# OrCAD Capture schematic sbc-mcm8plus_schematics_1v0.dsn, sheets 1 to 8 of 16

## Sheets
1 16. Misc: size A3; title: SBC-MCM8PLUS   16. Misc; rev: 1.0; note: 8000216000
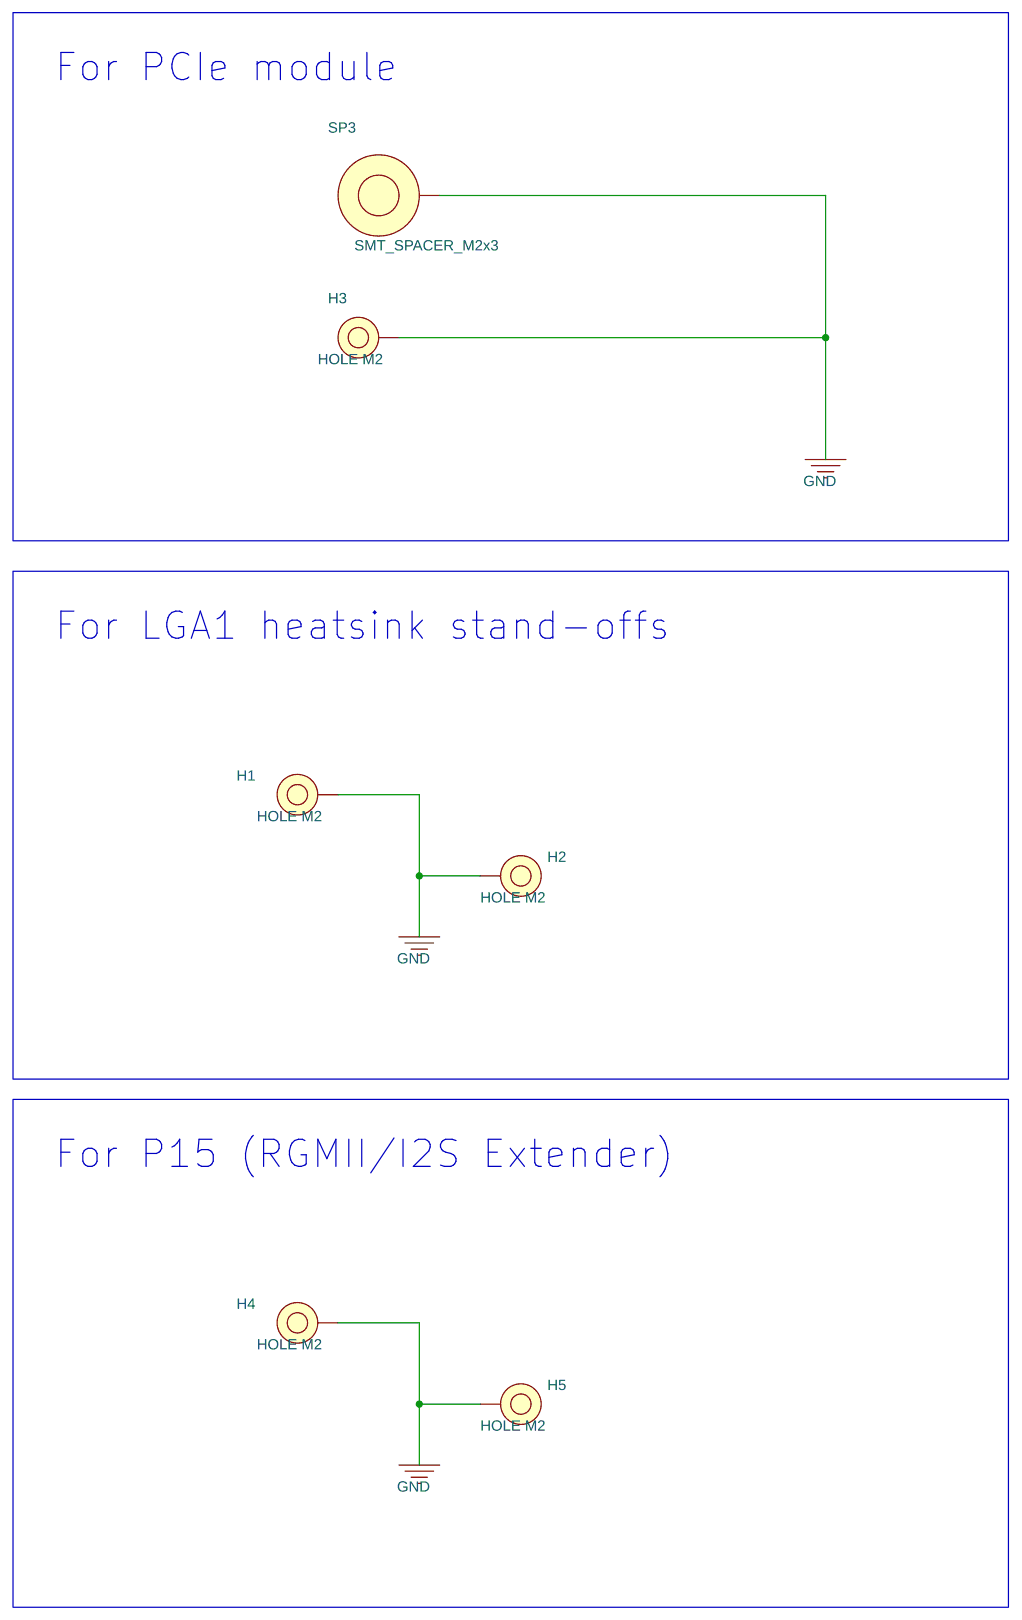
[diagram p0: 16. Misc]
2 03. Int Carrier-board interface: size A3; title: SBC-MCM8PLUS   03. Soldered Internal Interface
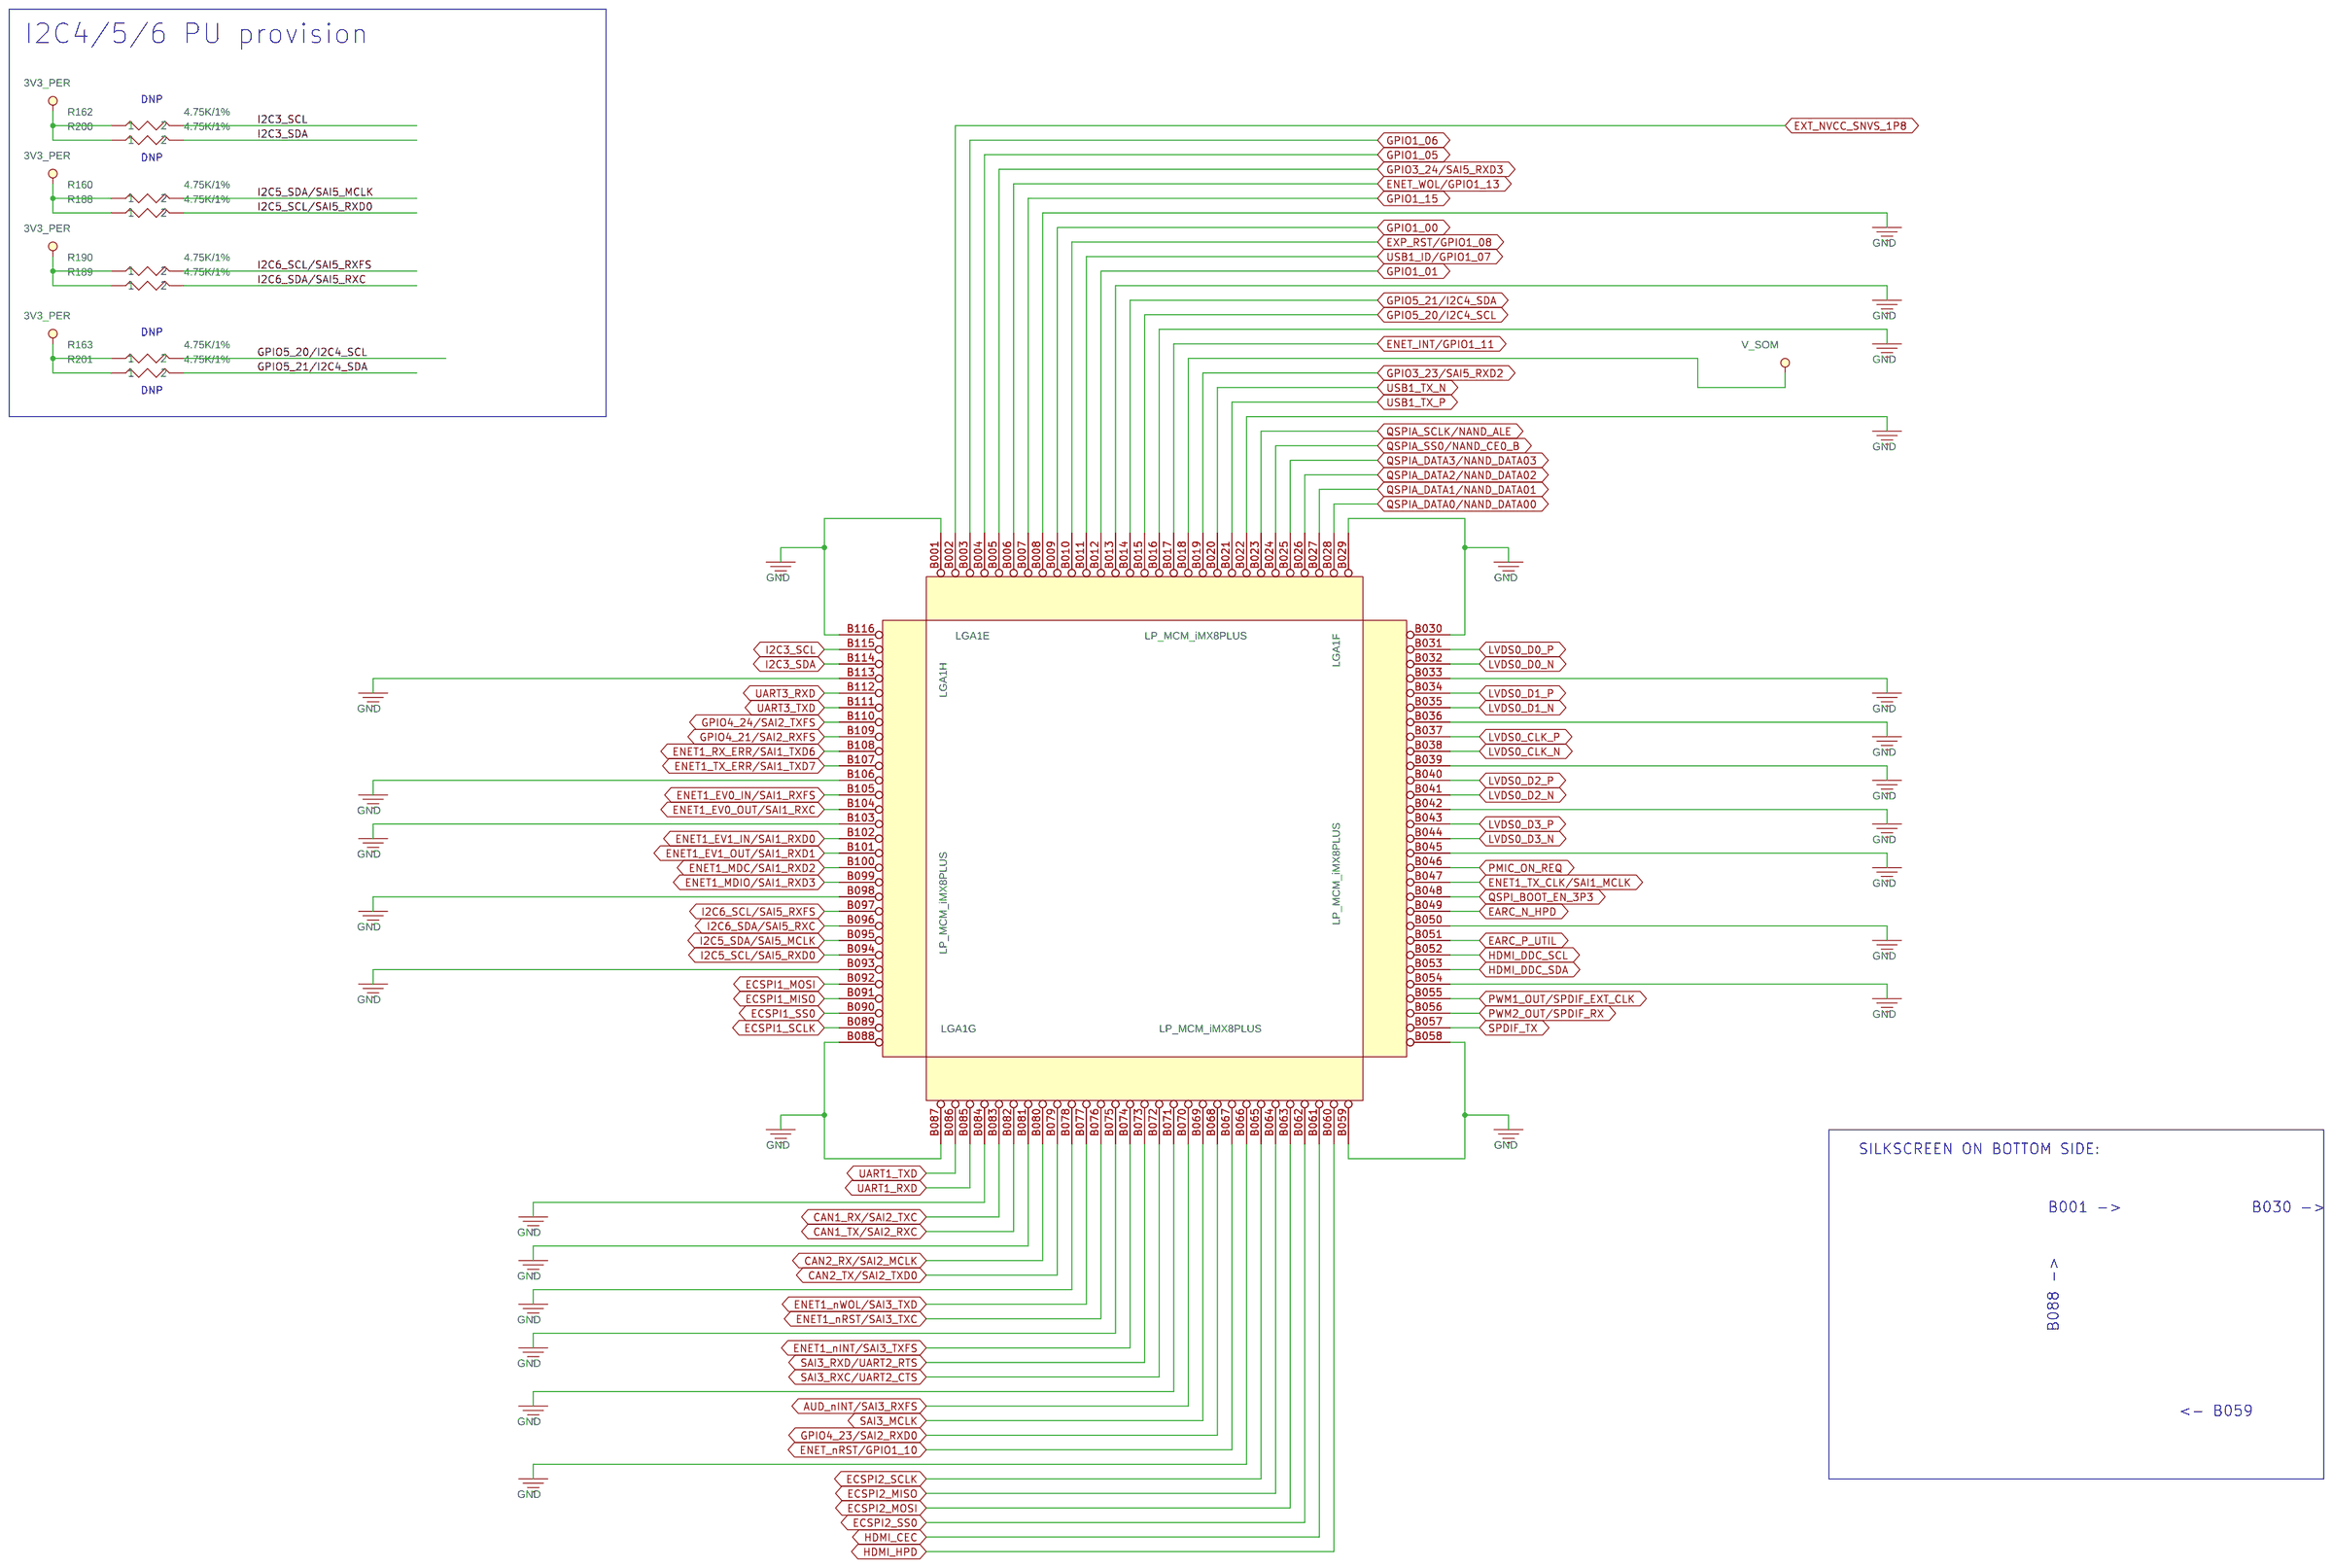
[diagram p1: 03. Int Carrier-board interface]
3 02. Ext Carrier-board interface: size A3; title: SBC-MCM8PLUS   02. Carrier
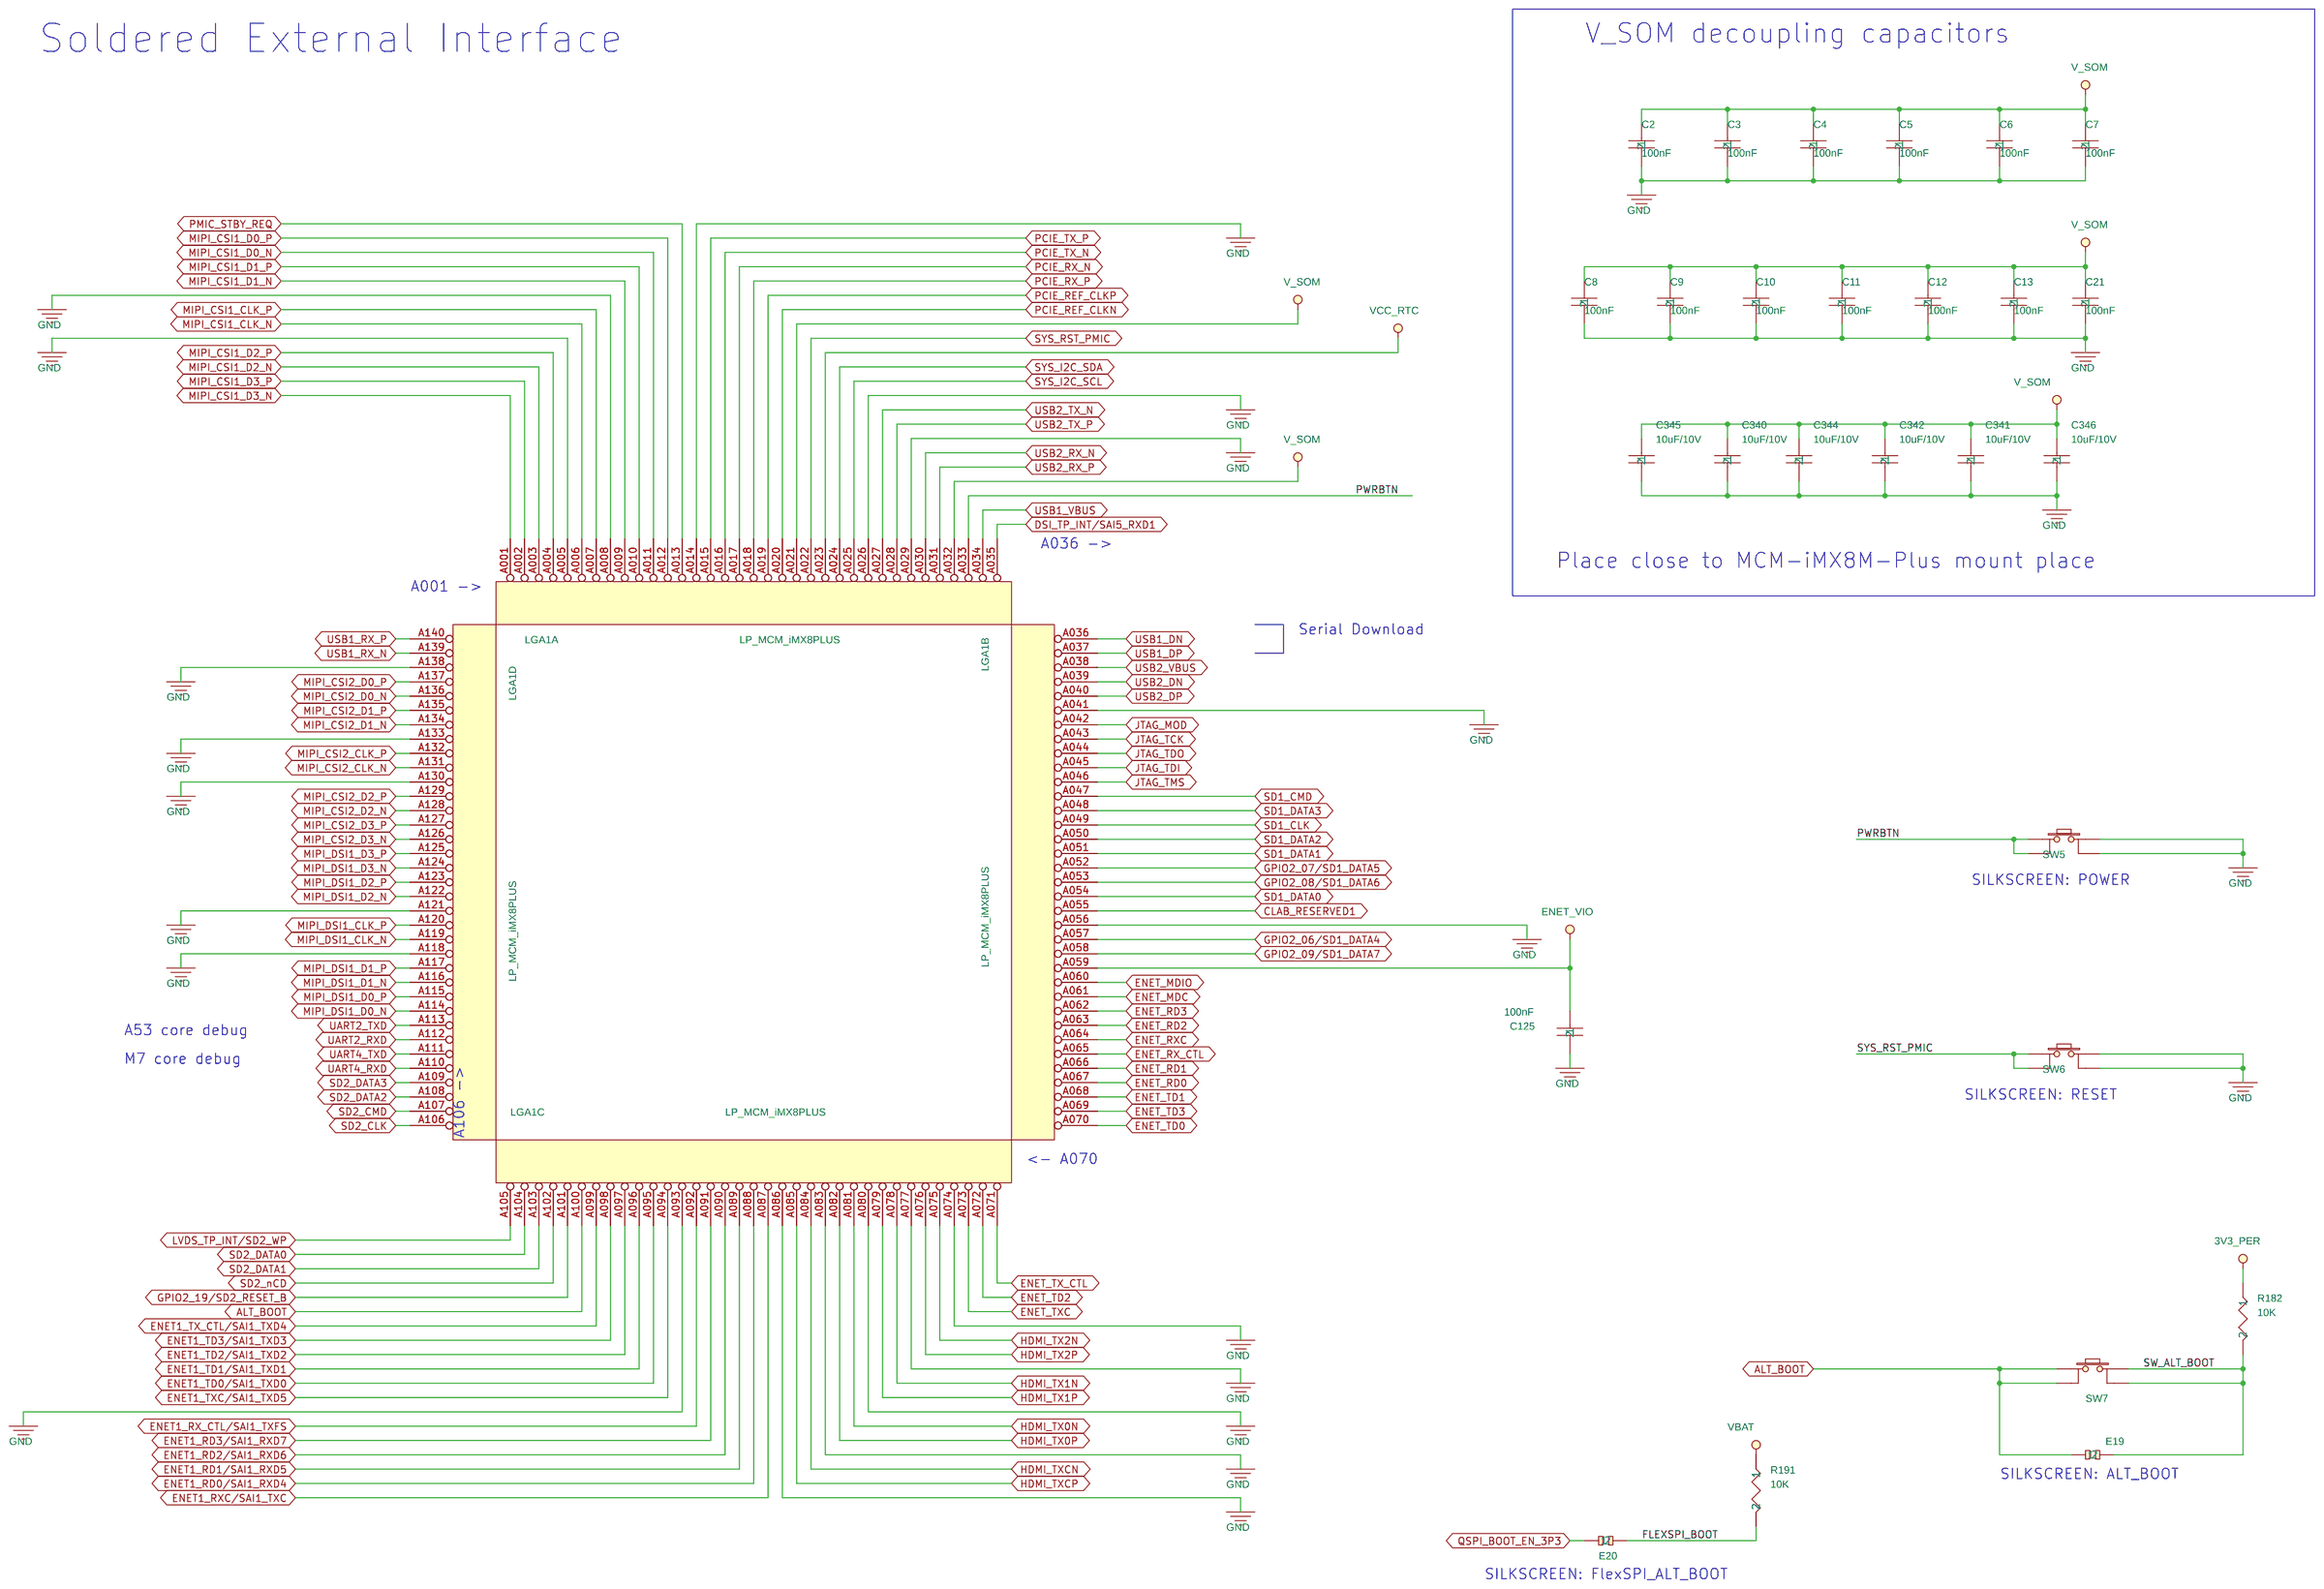
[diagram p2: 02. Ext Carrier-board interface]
4 11. MIPI-CSI2 Connectors: size A2; title: SBC-MCM8PLUS   11. MIPI-CSI2, GMSL Deserializer
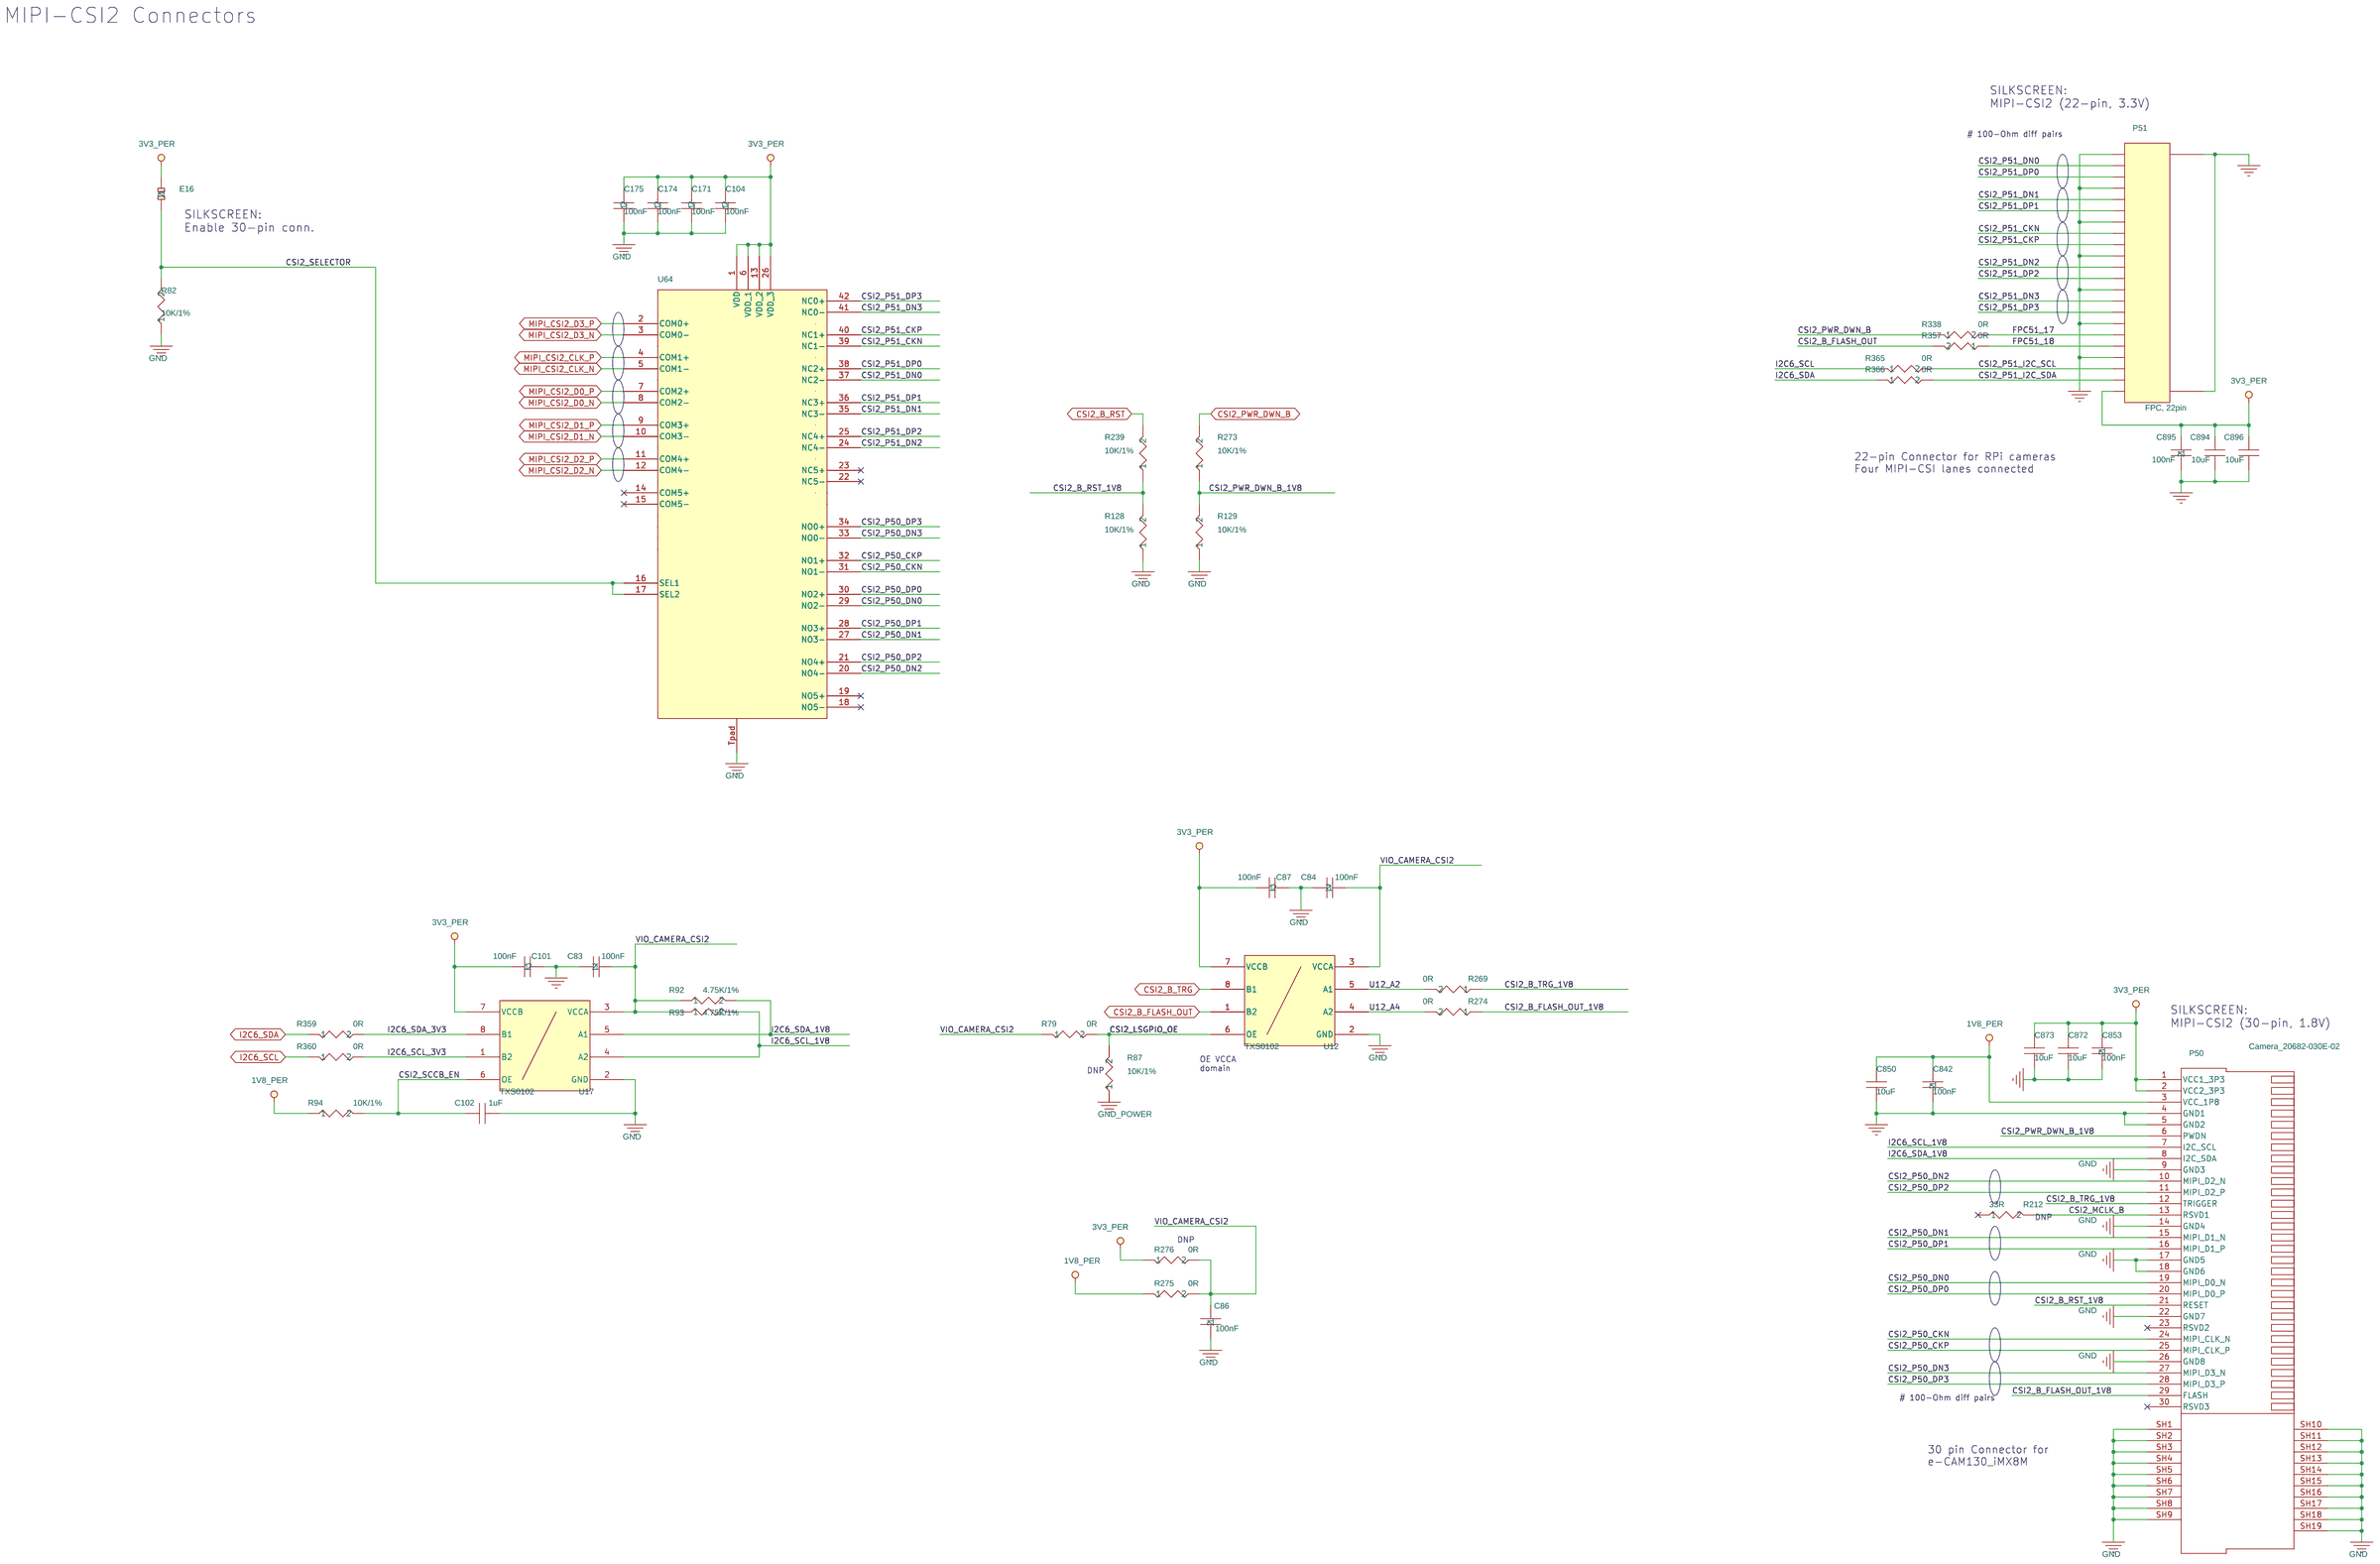
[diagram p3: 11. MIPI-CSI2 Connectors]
5 10. MIPI-CSI1 Connectors: size A3; title: SBC-MCM8PLUS   10. MIPI-CSI1 Connectors
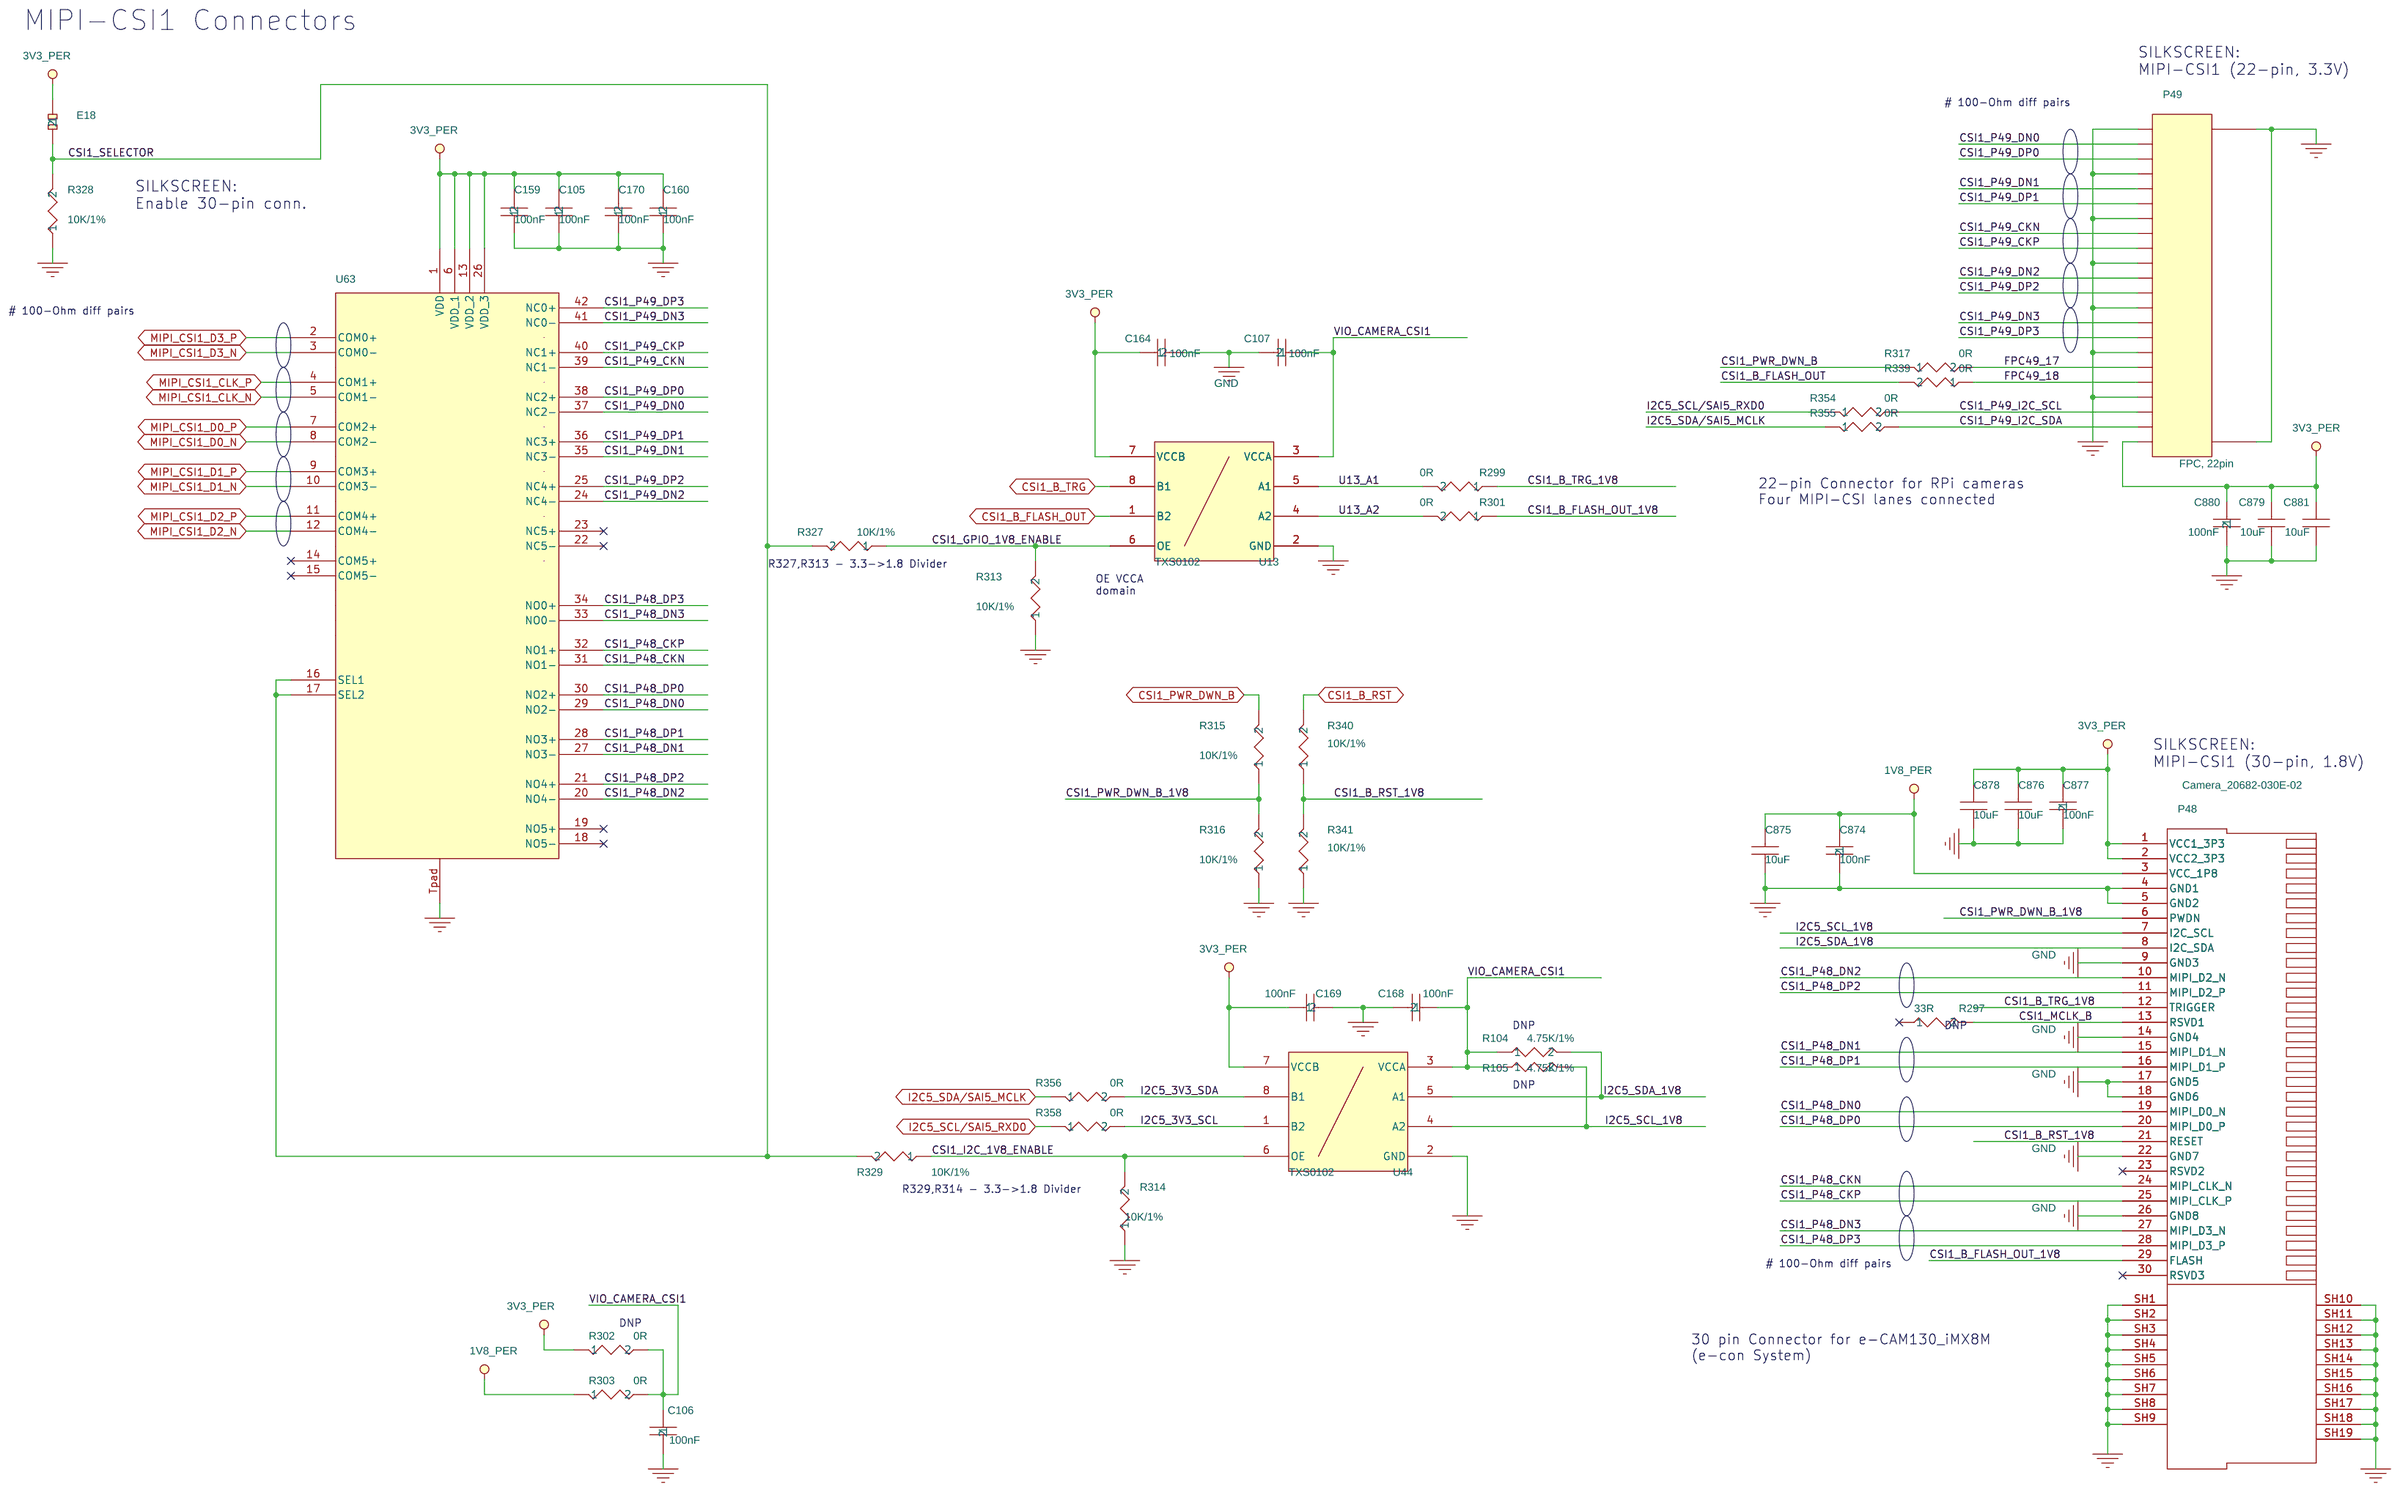
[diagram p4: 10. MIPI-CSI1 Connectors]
6 09. HDMI, eARC: size A3; title: SBC-MCM8PLUS   09. HDMI, eARC
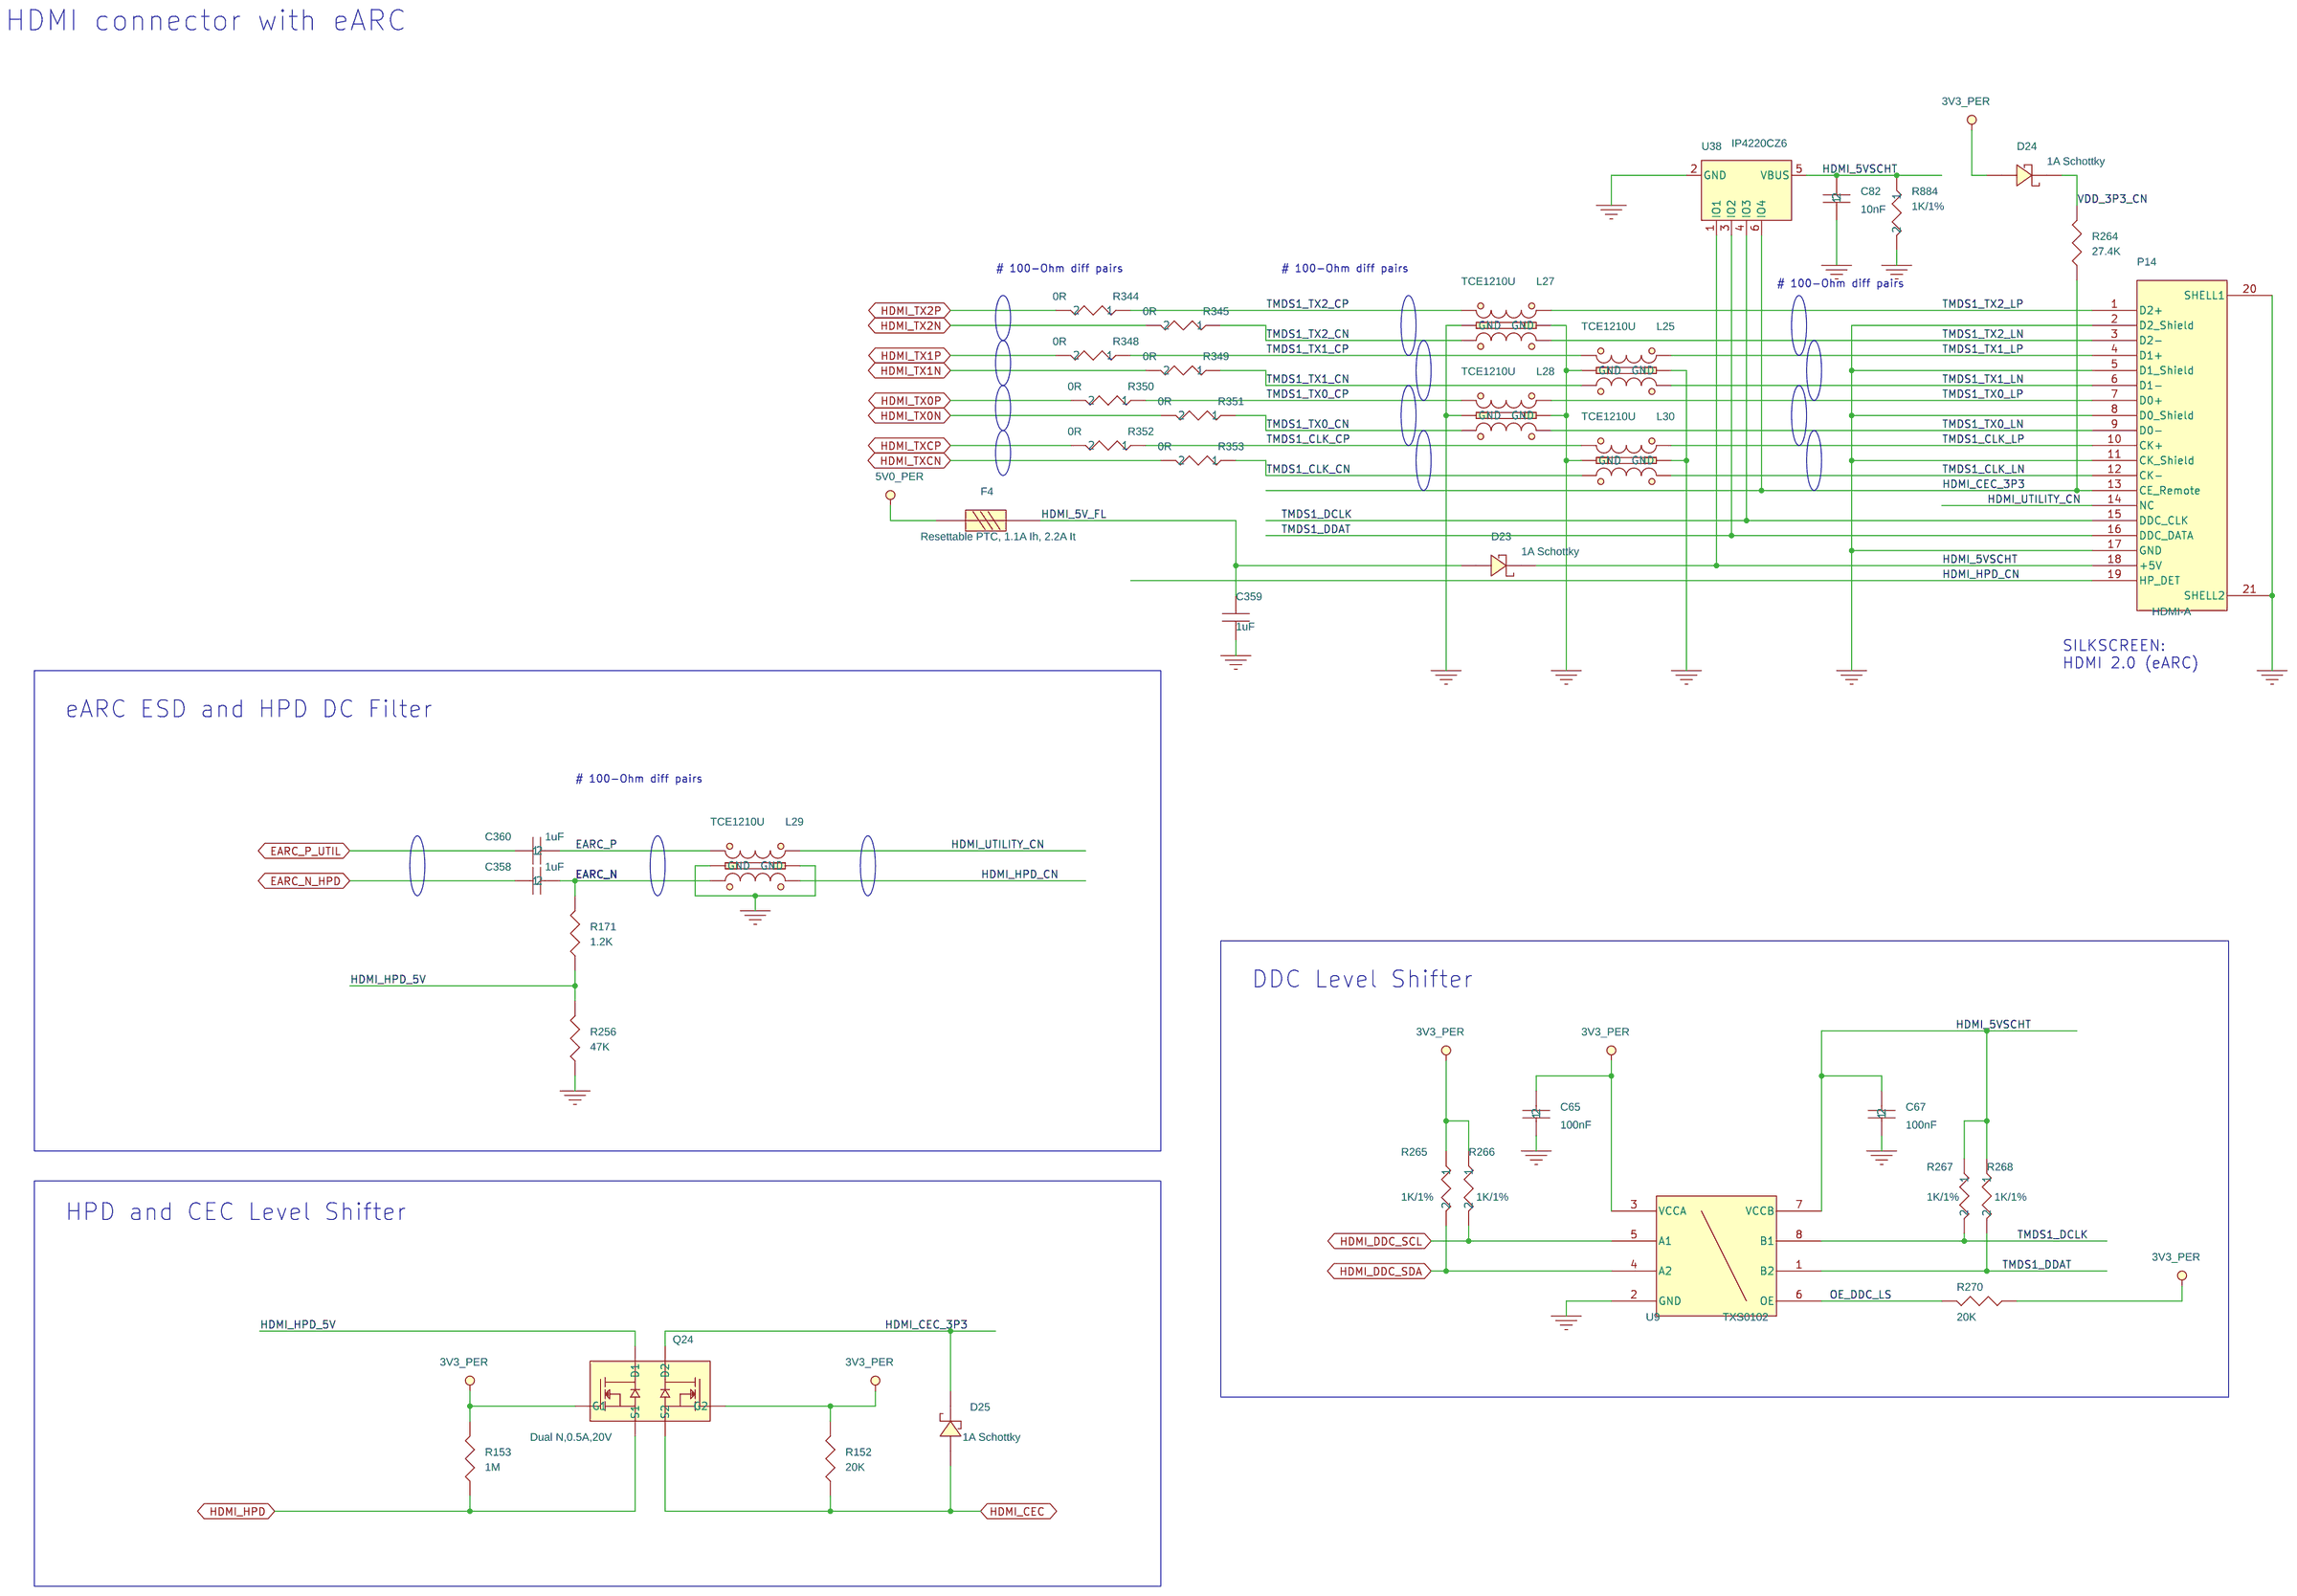
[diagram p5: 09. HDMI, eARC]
7 08. LVDS LCD: size A3; title: SBC-MCM8PLUS   08. LVDS LCD
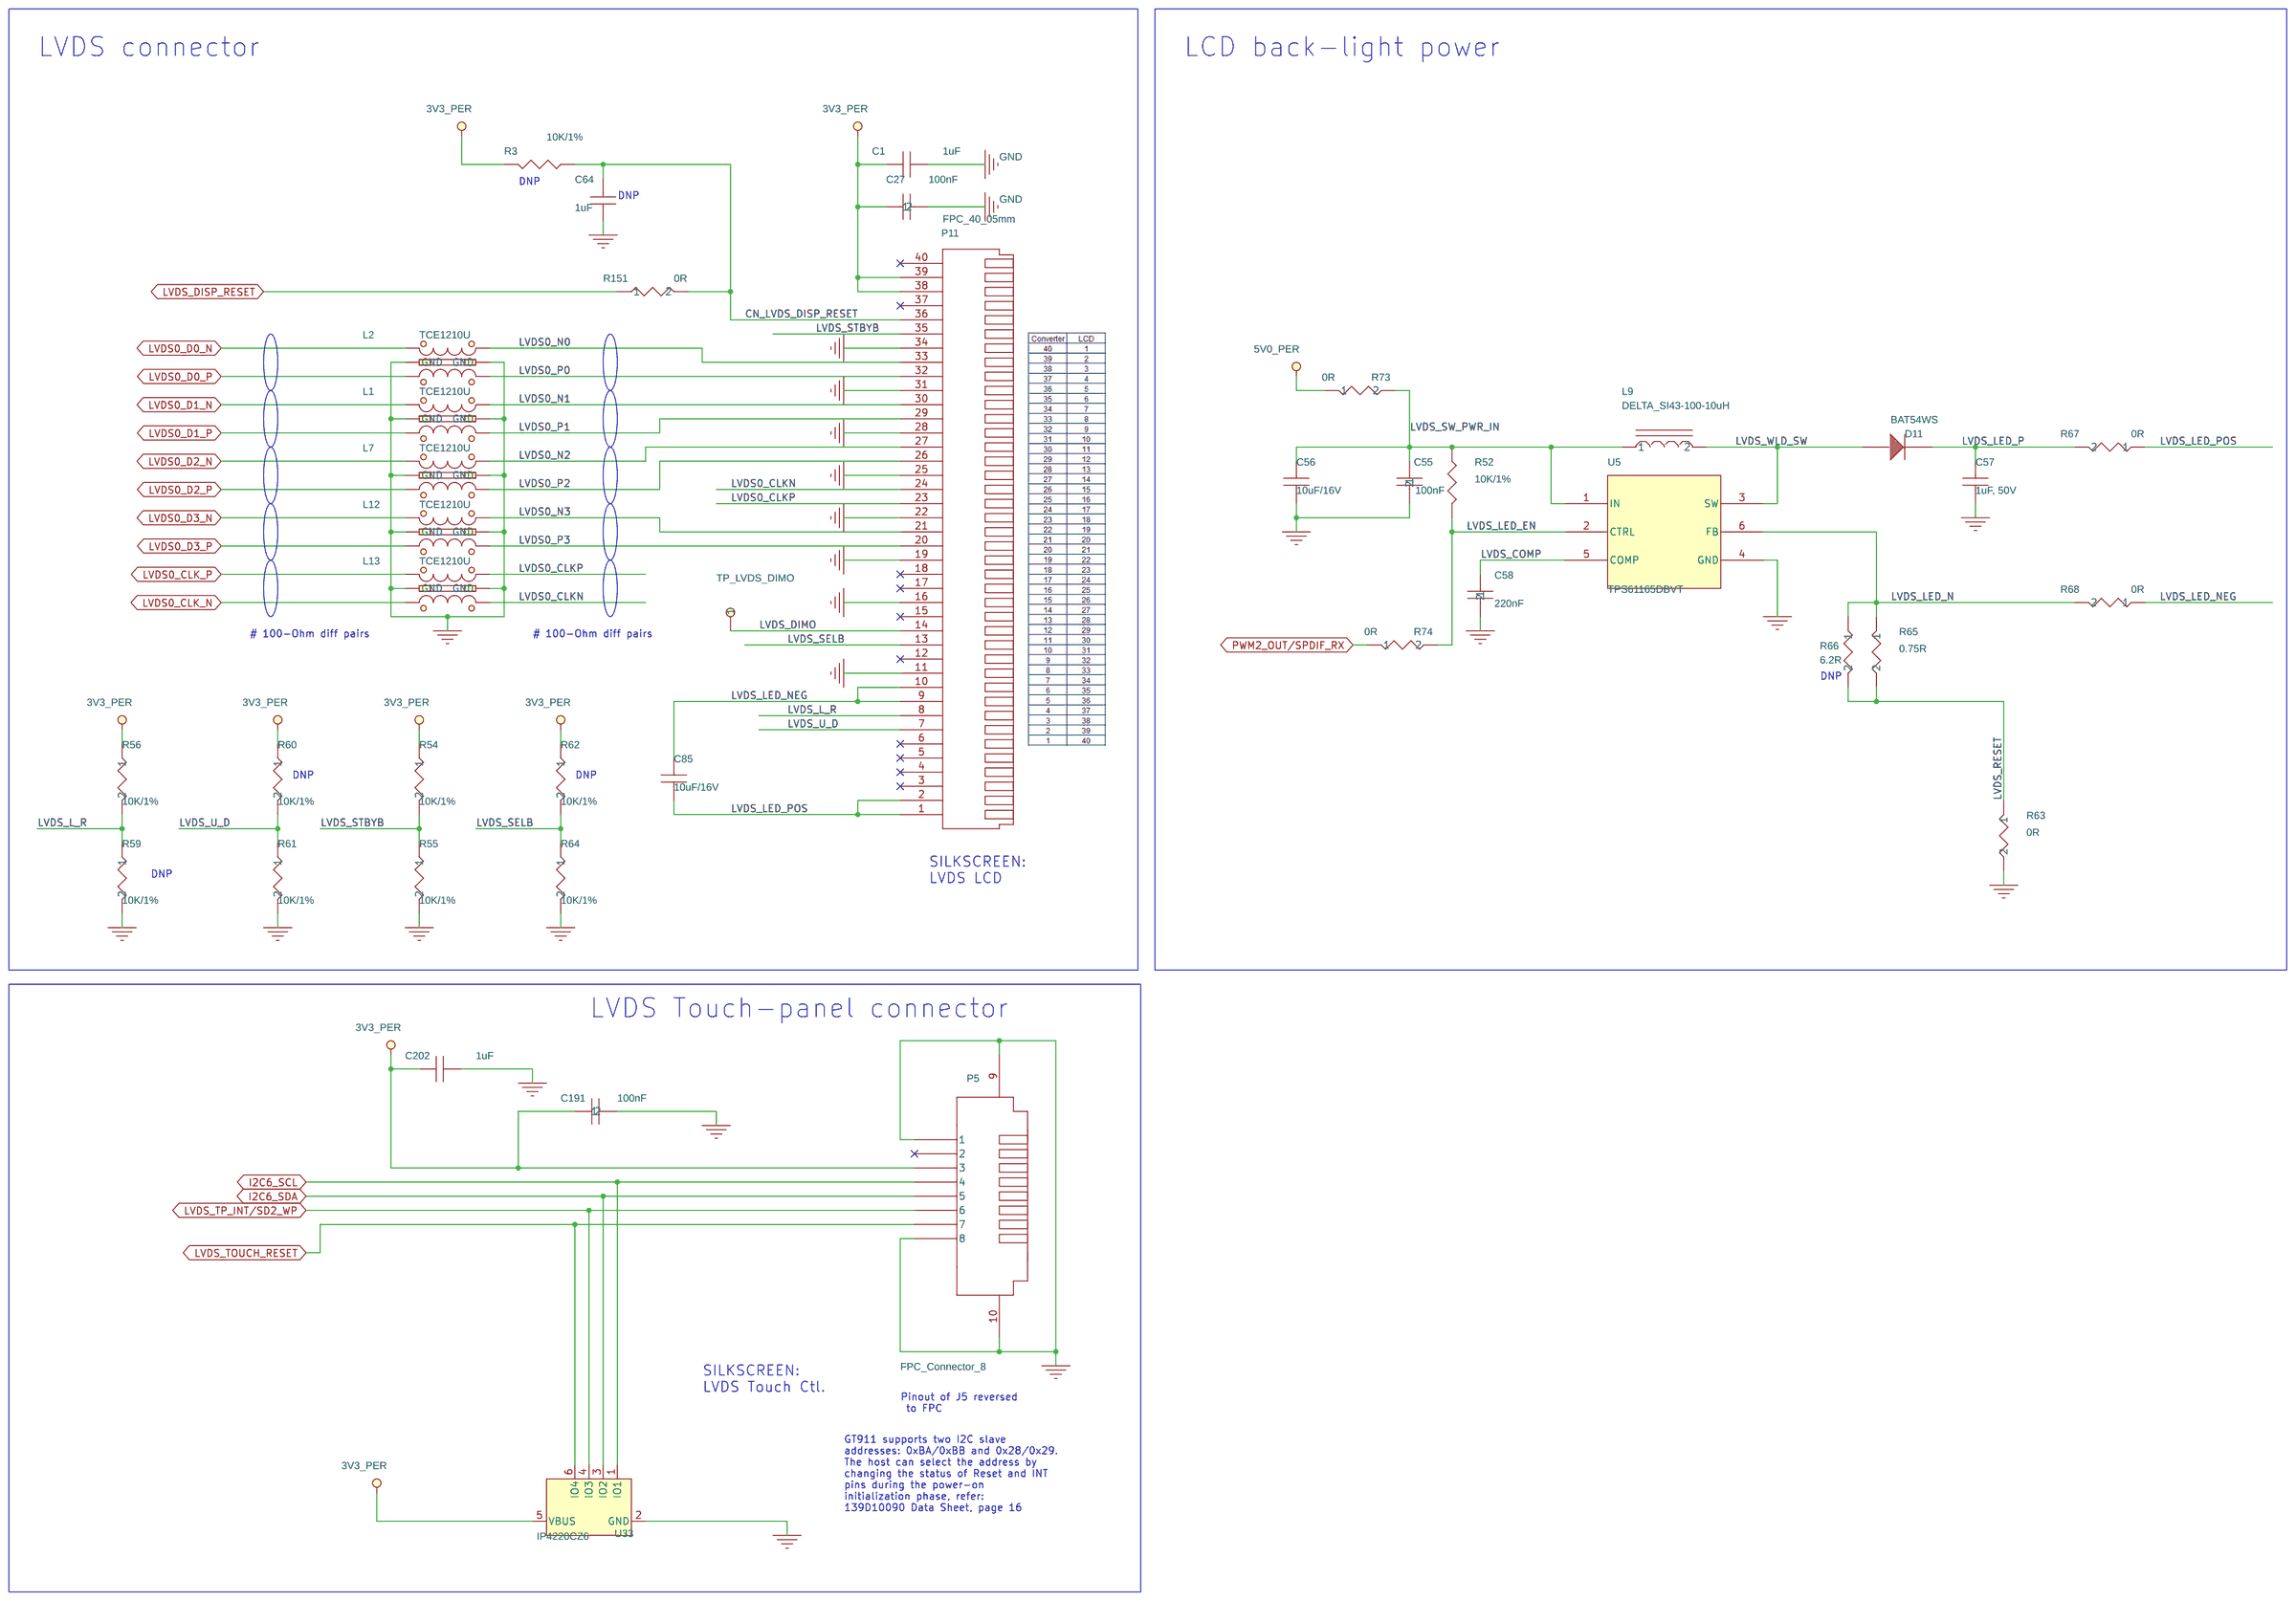
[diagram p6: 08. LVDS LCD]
8 01. Block Diagram: title: SBC-MCM8PLUS   01. INDEX
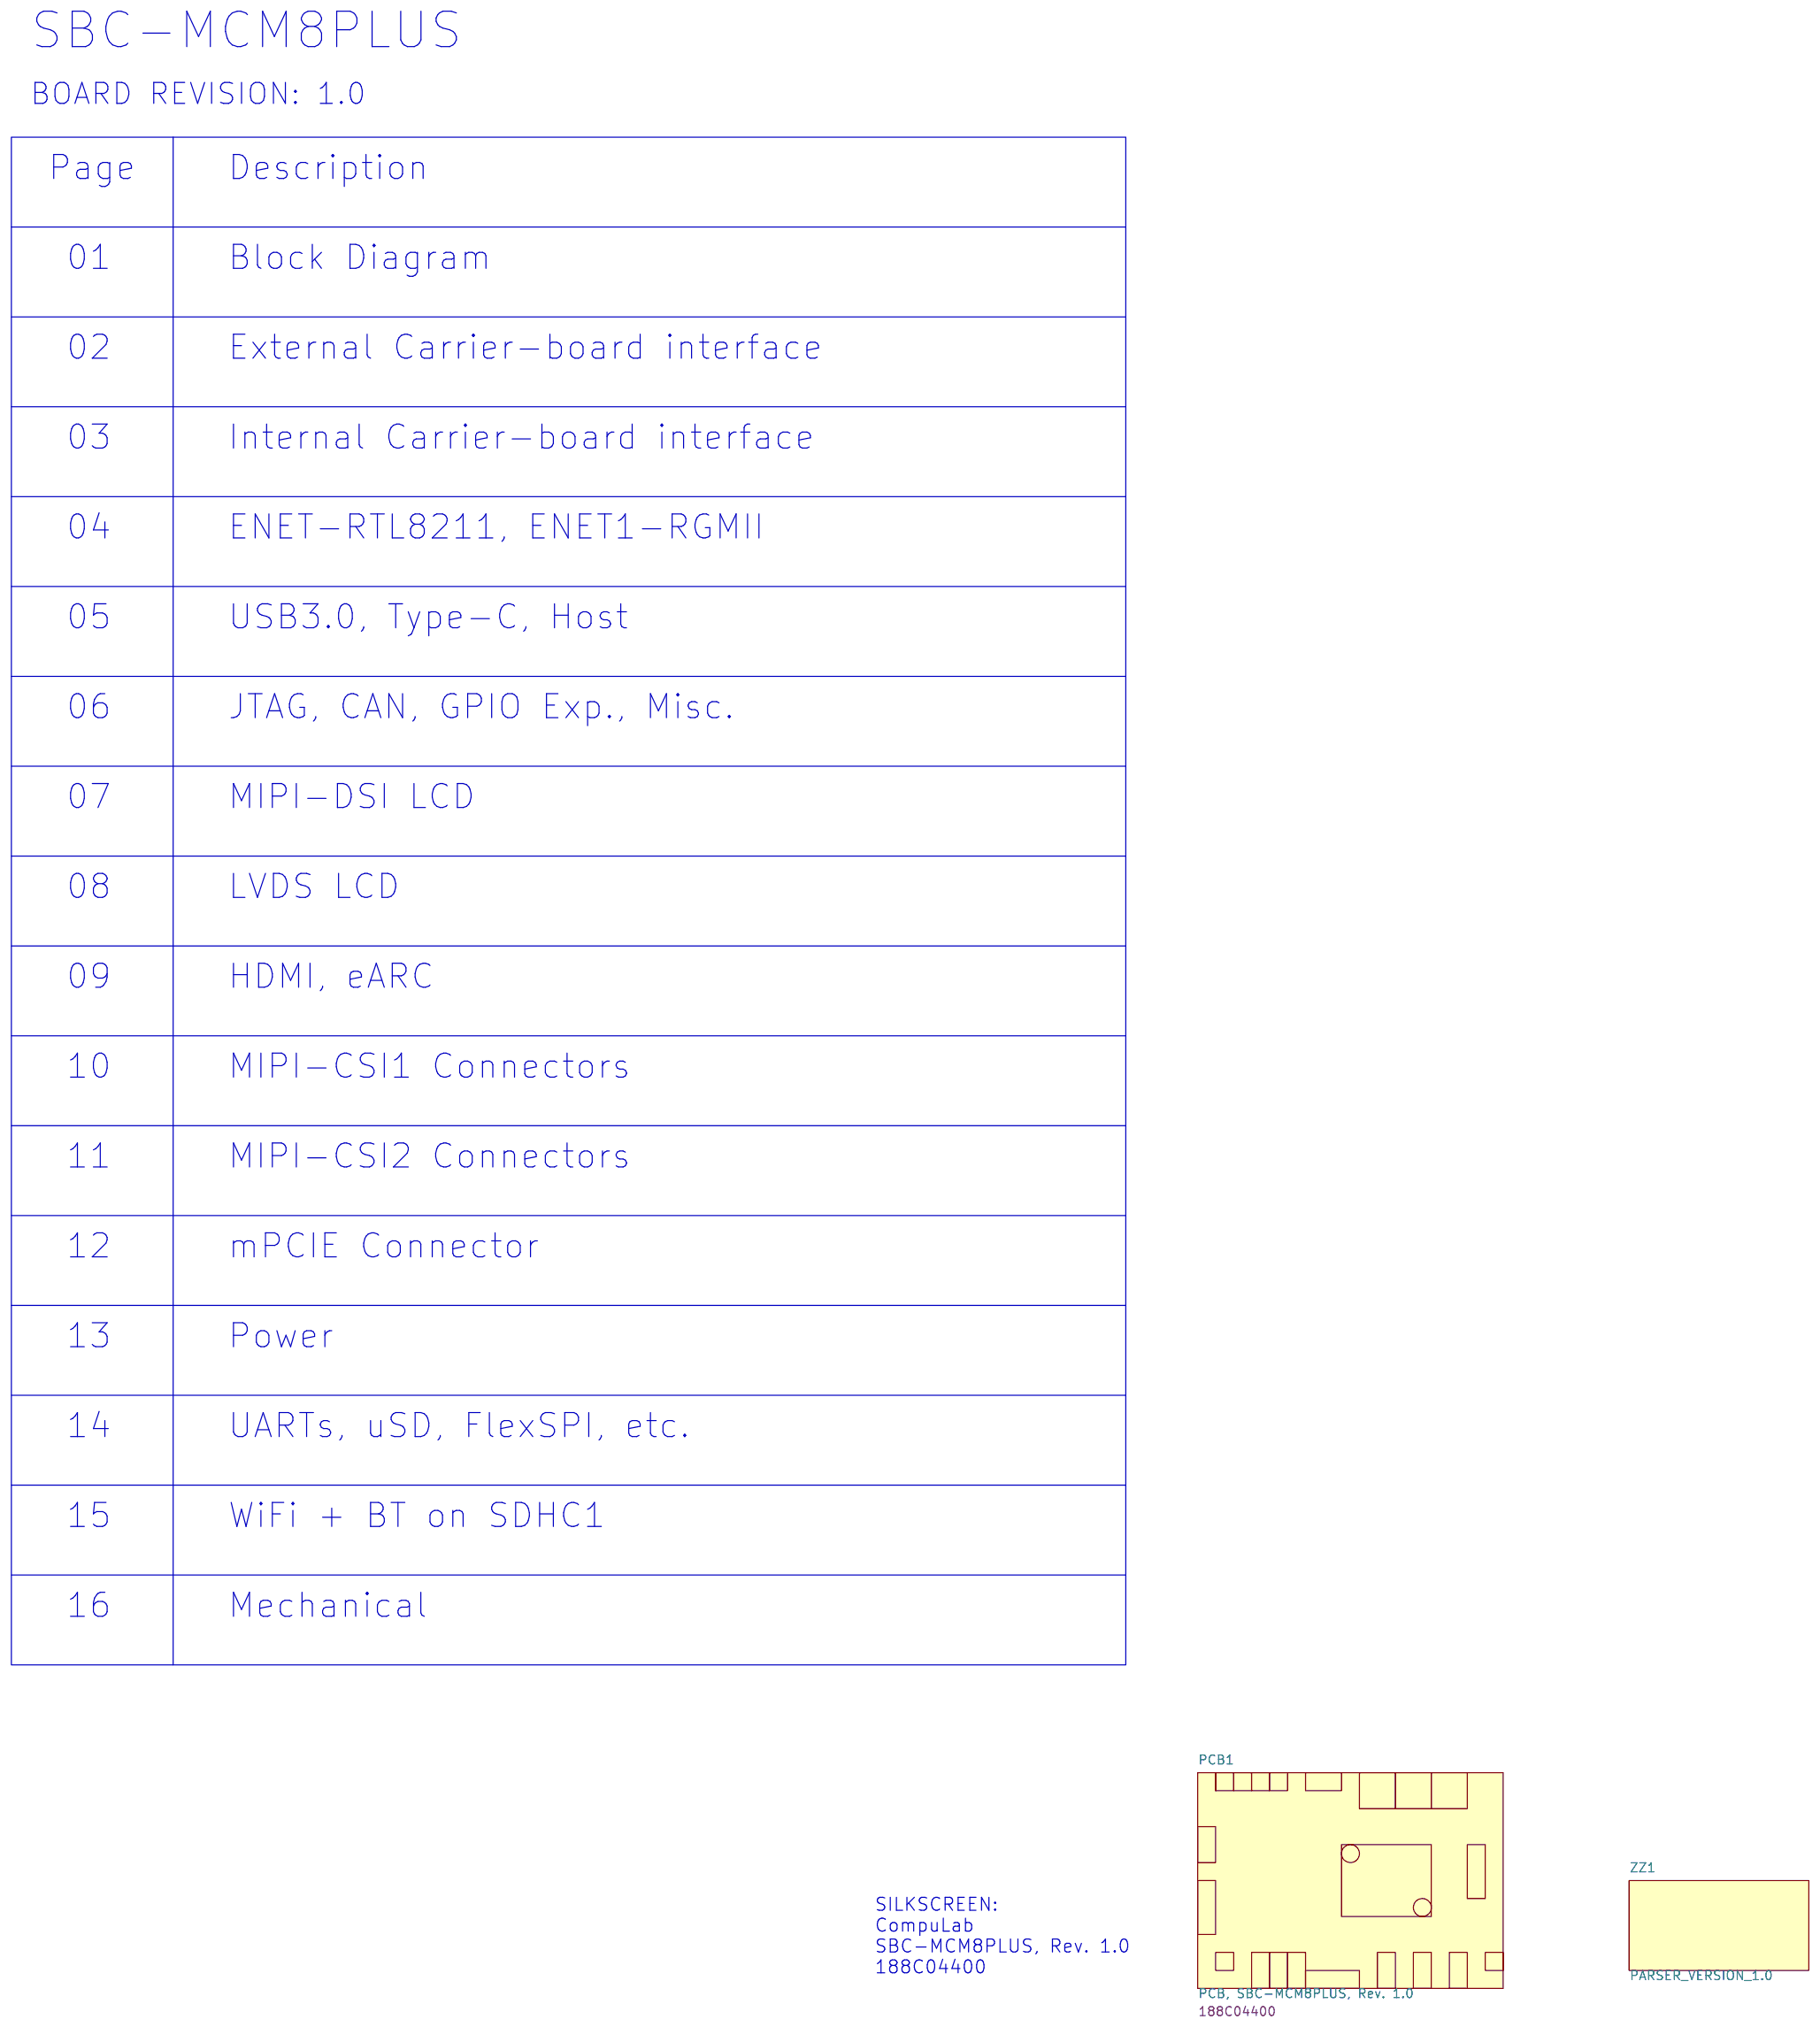
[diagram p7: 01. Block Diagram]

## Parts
sheet 01. Block Diagram
PCB1  PCB, SBC-MCM8PLUS, Rev. 1.0
ZZ1  PARSER_VERSION_1.0
sheet 02. Ext Carrier-board interface
C2  100nF  [RC0402]
C3  100nF  [RC0402]
C4  100nF  [RC0402]
C5  100nF  [RC0402]
C6  100nF  [RC0402]
C7  100nF  [RC0402]
C8  100nF  [RC0402]
C9  100nF  [RC0402]
C10  100nF  [RC0402]
C11  100nF  [RC0402]
C12  100nF  [RC0402]
C13  100nF  [RC0402]
C21  100nF  [RC0402]
C125  100nF  [RC0201]
C340  10uF/10V  [RC0402]
C341  10uF/10V  [RC0402]
C342  10uF/10V  [RC0402]
C344  10uF/10V  [RC0402]
C345  10uF/10V  [RC0402]
C346  10uF/10V  [RC0402]
E19  HDR1X2  [1X2THHDR]
E20  HDR1X2  [1X2THHDR]
R182  10K  [RC0402]
R191  10K  [RC0402]
SW5  PushB  [TACTSW6x6SM]
SW6  PushB  [TACTSW6x6SM]
SW7  PushB  [TACTSW6x6SM]
sheet 03. Int Carrier-board interface
LGA1  LP_MCM_iMX8PLUS  [LGA-256-080-30x30_Base]  (sections A,B,C,D,E,F,G,H)
R160  4.75K/1%  [RC0402]
R162  4.75K/1%  [RC0402]
R163  4.75K/1%  [RC0402]
R188  4.75K/1%  [RC0402]
R189  4.75K/1%  [RC0402]
R190  4.75K/1%  [RC0402]
R200  4.75K/1%  [RC0402]
R201  4.75K/1%  [RC0402]
sheet 08. LVDS LCD
C1  1uF  [RC0402]
C27  100nF  [RC0402]
C55  100nF  [RC0402]
C56  10uF/16V  [RC0603]
C57  1uF, 50V  [RC0603]
C58  220nF  [RC0402]
C64  1uF  [RC0402]
C85  10uF/16V  [RC0603]
C191  100nF  [RC0402]
C202  1uF  [RC0402]
D11  BAT54WS  [SOD-323]
L1  TCE1210U  [EMI1012-ESD]
L2  TCE1210U  [EMI1012-ESD]
L7  TCE1210U  [EMI1012-ESD]
L9  DELTA_SI43-100-10uH  [IND4x4x2_5]
L12  TCE1210U  [EMI1012-ESD]
L13  TCE1210U  [EMI1012-ESD]
P5  FPC_Connector_8  [FPC_8]
P11  FPC_40_05mm  [FPC05SM40-1]
R3  10K/1%  [RC0402]
R52  10K/1%  [RC0402]
R54  10K/1%  [RC0402]
R55  10K/1%  [RC0402]
R56  10K/1%  [RC0402]
R59  10K/1%  [RC0402]
R60  10K/1%  [RC0402]
R61  10K/1%  [RC0402]
R62  10K/1%  [RC0402]
R63  0R  [RC0402]
R64  10K/1%  [RC0402]
R65  0.75R  [RC0402]
R66  6.2R  [RC0402]
R67  0R  [RC1206]
R68  0R  [RC1206]
R73  0R  [RC1206]
R74  0R  [RC1206]
R151  0R  [RC0402]
TP_LVDS_DIMO  TESTPOINT  [TESTPOINT]
U5  TPS61165DBVT  [SOT23-6]
U33  IP4220CZ6  [SOT23-6L]
sheet 09. HDMI, eARC
C65  100nF  [RC0402]
C67  100nF  [RC0402]
C82  10nF  [RC0402]
C358  1uF  [RC0402]
C359  1uF  [RC0402]
C360  1uF  [RC0402]
D23  1A Schottky  [SOD-123]
D24  1A Schottky  [SOD-123]
D25  1A Schottky  [SOD-123]
F4  Resettable PTC, 1.1A Ih, 2.2A It  [FUSE-1206]
L25  TCE1210U  [EMI1012-ESD]
L27  TCE1210U  [EMI1012-ESD]
L28  TCE1210U  [EMI1012-ESD]
L29  TCE1210U  [EMI1012-ESD]
L30  TCE1210U  [EMI1012-ESD]
P14  HDMI-A  [SMT(HDMI-A)]
Q24  Dual N,0.5A,20V  [SOT-563-6]
R152  20K  [RC0402]
R153  1M  [RC0402]
R171  1.2K  [RC0402]
R256  47K  [RC0402]
R264  27.4K  [RC0402]
R265  1K/1%  [RC0402]
R266  1K/1%  [RC0402]
R267  1K/1%  [RC0402]
R268  1K/1%  [RC0402]
R270  20K  [RC0402]
R344  0R  [RC0402]
R345  0R  [RC0402]
R348  0R  [RC0402]
R349  0R  [RC0402]
R350  0R  [RC0402]
R351  0R  [RC0402]
R352  0R  [RC0402]
R353  0R  [RC0402]
R884  1K/1%  [RC0402]
U9  TXS0102  [MO-187DA-8]
U38  IP4220CZ6  [SOT23-6L]
sheet 10. MIPI-CSI1 Connectors
C105  100nF  [RC0402]
C106  100nF  [RC0402]
C107  100nF  [RC0402]
C159  100nF  [RC0402]
C160  100nF  [RC0402]
C164  100nF  [RC0402]
C168  100nF  [RC0402]
C169  100nF  [RC0402]
C170  100nF  [RC0402]
C874  100nF  [RC0402]
C875  10uF  [RC0603]
C876  10uF  [RC0603]
C877  100nF  [RC0402]
C878  10uF  [RC0603]
C879  10uF  [RC0603]
C880  100nF  [RC0402]
C881  10uF  [RC0603]
E18  HDR1X2  [1X2THHDR]
P48  Camera_20682-030E-02  [CON30]
P49  FPC, 22pin  [FPC05SM22]
R104  4.75K/1%  [RC0402]
R105  4.75K/1%  [RC0402]
R297  33R  [RC0402]
R299  0R  [RC0402]
R301  0R  [RC0402]
R302  0R  [RC0402]
R303  0R  [RC0402]
R313  10K/1%  [RC0402]
R314  10K/1%  [RC0402]
R315  10K/1%  [RC0402]
R316  10K/1%  [RC0402]
R317  0R  [RC0402]
R327  10K/1%  [RC0402]
R328  10K/1%  [RC0402]
R329  10K/1%  [RC0402]
R339  0R  [RC0402]
R340  10K/1%  [RC0402]
R341  10K/1%  [RC0402]
R354  0R  [RC0402]
R355  0R  [RC0402]
R356  0R  [RC0402]
R358  0R  [RC0402]
U13  TXS0102  [MO-187DA-8]
U44  TXS0102  [MO-187DA-8]
U63  Value  [21-0181B_T423590M-1_MXM]
sheet 11. MIPI-CSI2 Connectors
C83  100nF  [RC0402]
C84  100nF  [RC0402]
C86  100nF  [RC0402]
C87  100nF  [RC0402]
C101  100nF  [RC0402]
C102  1uF  [RC0402]
C104  100nF  [RC0402]
C171  100nF  [RC0402]
C174  100nF  [RC0402]
C175  100nF  [RC0402]
C842  100nF  [RC0402]
C850  10uF  [RC0603]
C853  100nF  [RC0402]
C872  10uF  [RC0603]
C873  10uF  [RC0603]
C894  10uF  [RC0603]
C895  100nF  [RC0402]
C896  10uF  [RC0603]
E16  HDR1X2  [1X2THHDR]
P50  Camera_20682-030E-02  [CON30]
P51  FPC, 22pin  [FPC05SM22]
R79  0R  [RC0402]
R82  10K/1%  [RC0402]
R87  10K/1%  [RC0402]
R92  4.75K/1%  [RC0402]
R93  4.75K/1%  [RC0402]
R94  10K/1%  [RC0402]
R128  10K/1%  [RC0402]
R129  10K/1%  [RC0402]
R212  33R  [RC0402]
R239  10K/1%  [RC0402]
R269  0R  [RC0402]
R273  10K/1%  [RC0402]
R274  0R  [RC0402]
R275  0R  [RC0402]
R276  0R  [RC0402]
R338  0R  [RC0402]
R357  0R  [RC0402]
R359  0R  [RC0402]
R360  0R  [RC0402]
R365  0R  [RC0402]
R366  0R  [RC0402]
U12  TXS0102  [MO-187DA-8]
U17  TXS0102  [MO-187DA-8]
U64  Value  [21-0181B_T423590M-1_MXM]
sheet 16. Misc
H1  HOLE M2  [M2PAD]
H2  HOLE M2  [M2PAD]
H3  HOLE M2  [M2PAD]
H4  HOLE M2  [M2PAD]
H5  HOLE M2  [M2PAD]
SP3  SMT_SPACER_M2x3  [MINIPCIE-4-Spacer]

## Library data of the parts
PCB1 = PCB,_EM-X270_Rev_1_6.1: CLABCONF0: = SBC-MCM8PLUS; P/N: 188C04400
ZZ1 = PARSER_VERSION_1_1.0: CLABCONF0: DNP
C2 = 100nF,_10V,_X7R,_10%,_0402_13: CLABCONF0: = SBC-MCM8PLUS; P/N: 151B10400S
C3 = 100nF,_10V,_X7R,_10%,_0402_2: CLABCONF0: = SBC-MCM8PLUS; P/N: 151B10400S
C4 = 100nF,_10V,_X7R,_10%,_0402: CLABCONF0: = SBC-MCM8PLUS; P/N: 151B10400S
C5 = 100nF,_10V,_X7R,_10%,_0402_3: CLABCONF0: = SBC-MCM8PLUS; P/N: 151B10400S
C6 = 100nF,_10V,_X7R,_10%,_0402_5: CLABCONF0: = SBC-MCM8PLUS; P/N: 151B10400S
C7 = 100nF,_10V,_X7R,_10%,_0402_6: CLABCONF0: = SBC-MCM8PLUS; P/N: 151B10400S
C8 = 100nF,_10V,_X7R,_10%,_0402_8: CLABCONF0: = SBC-MCM8PLUS; P/N: 151B10400S
C9 = 100nF,_10V,_X7R,_10%,_0402_9: CLABCONF0: = SBC-MCM8PLUS; P/N: 151B10400S
C10 = 100nF,_10V,_X7R,_10%,_0402_7: CLABCONF0: = SBC-MCM8PLUS; P/N: 151B10400S
C11 = 100nF,_10V,_X7R,_10%,_0402_10: CLABCONF0: = SBC-MCM8PLUS; P/N: 151B10400S
C12 = 100nF,_10V,_X7R,_10%,_0402_12: CLABCONF0: = SBC-MCM8PLUS; P/N: 151B10400S
C13 = 100nF,_10V,_X7R,_10%,_0402_1: CLABCONF0: = SBC-MCM8PLUS; P/N: 151B10400S
C21 = 100nF,_10V,_X7R,_10%,_0402_4: CLABCONF0: = SBC-MCM8PLUS; P/N: 151B10400S
C125 = 100nF,_10V,_X7R,_10%,_0402_11: CLABCONF0: = SBC-MCM8PLUS; P/N: 151B104B0S
C340 = 10uF_10V_20%_0402_3: CLABCONF0: = SBC-MCM8PLUS
C341 = 10uF_10V_20%_0402_5: CLABCONF0: = SBC-MCM8PLUS
C342 = 10uF_10V_20%_0402: CLABCONF0: = SBC-MCM8PLUS
C344 = 10uF_10V_20%_0402_4: CLABCONF0: = SBC-MCM8PLUS
C345 = 10uF_10V_20%_0402_1: CLABCONF0: = SBC-MCM8PLUS
C346 = 10uF_10V_20%_0402_2: CLABCONF0: = SBC-MCM8PLUS
E19 = HDR_1x2_100MIL_TH_JUMPER_1: CLABCONF0: = SBC-MCM8PLUS
E16 E18 E20 = HDR_1x2_100MIL_TH_JUMPER: CLABCONF0: = SBC-MCM8PLUS
R182 = 1M_,5%,_0402: CLABCONF0: = SBC-MCM8PLUS; P/N: 161C10021S
R191 = 1M_,5%,_0402_1: CLABCONF0: = SBC-MCM8PLUS; P/N: 161C10021S
SW5-SW7 = TACT_SW_6x6mm_SMT: CLABCONF0: = SBC-MCM8PLUS
LGA1 = LP_MCM_iMX8PLUS: CLABCONF0: 503M015060=CQMD4N32; Color: Default; Location X-Coordinate: 0; Location Y-Coordinate: 0; P/N: 503M015060; Power Pins Visible: False; Primitive: DEFAULT
R160 = 4_0.75K,1%,0402,1_16W_2: CLABCONF0: = SBC-MCM8PLUS
R104 R162 = 4_0.75K,1%,0402,1_16W_1: CLABCONF0: DNP
R163 = 4_0.75K,1%,0402,1_16W_7: CLABCONF0: DNP
R188 = 4_0.75K,1%,0402,1_16W_3: CLABCONF0: = SBC-MCM8PLUS
R189 = 4_0.75K,1%,0402,1_16W_4: CLABCONF0: = SBC-MCM8PLUS
R190 = 4_0.75K,1%,0402,1_16W_6: CLABCONF0: = SBC-MCM8PLUS
R105 R200 = 4_0.75K,1%,0402,1_16W: CLABCONF0: DNP
R201 = 4_0.75K,1%,0402,1_16W_5: CLABCONF0: DNP
C1 C102 C202 = 1uF,X5R,6.3V,0402: CLABCONF0: = SBC-MCM8PLUS
C27 C174 C874 = 100nF,_10V,_X7R,_10%,_0402: CLABCONF0: = SBC-MCM8PLUS
C55 C65 C169 C842 = 100nF,_10V,_X7R,_10%,_0402_3: CLABCONF0: = SBC-MCM8PLUS
C56 = 10uF,6.3V,0603,20%X5R_1: CLABCONF0: = SBC-MCM8PLUS
C57 = 1uF,X5R,6.3V,0402: CLABCONF0: = SBC-MCM8PLUS; P/N: 151D10510S
C58 = 100nF,_10V,_X7R,_10%,_0402_2: CLABCONF0: = SBC-MCM8PLUS; P/N: 151C22400S
C64 = 1uF,X5R,6.3V,0402: CLABCONF0: DNP
C85 = 10uF,6.3V,0603,20%X5R: CLABCONF0: = SBC-MCM8PLUS
C67 C160 C175 C191 = 100nF,_10V,_X7R,_10%,_0402_1: CLABCONF0: = SBC-MCM8PLUS
D11 = BAT54WS_0: CLABCONF0: = SBC-MCM8PLUS
L1 L2 L7 L12 L13 L25 L27-L30 = ESD_CHOKE_DIFFx2_10: CLABCONF0: = SBC-MCM8PLUS; P/N: 142D11801S
L9 = INC_DELTA_SI43-100,_10uH: CLABCONF0: = SBC-MCM8PLUS; CLABCONF1: <null>
P5 = FPC_Connector_6: CLABCONF0: = SBC-MCM8PLUS; P/N: 182P00803S
P11 = FPC_40_05mm: CLABCONF0: = SBC-MCM8PLUS; P/N: 182P04001S
R3 = 10K,1%,0402,1_16W_0_1: CLABCONF0: DNP
R52 = 10K,1%,0402,1_16W_0: CLABCONF0: = SBC-MCM8PLUS
R54 R129 R329 = 10K,1%,0402,1_16W_3: CLABCONF0: = SBC-MCM8PLUS
R55 = 10K,1%,0402,1_16W_5: CLABCONF0: DNP
R56 R273 R341 = 10K,1%,0402,1_16W_6: CLABCONF0: = SBC-MCM8PLUS
R59 = 10K,1%,0402,1_16W_7: CLABCONF0: DNP
R60 R87 = 10K,1%,0402,1_16W: CLABCONF0: DNP
R61 R82 R316 = 10K,1%,0402,1_16W_1: CLABCONF0: = SBC-MCM8PLUS
R62 = 10K,1%,0402,1_16W_2: CLABCONF0: DNP
R63 = 2.2R,5%,0402,1_16W_1: CLABCONF0: = SBC-MCM8PLUS; P/N: 161C00005S
R64 R239 R327 = 10K,1%,0402,1_16W_4: CLABCONF0: = SBC-MCM8PLUS
R65 = 2.2R,5%,0402,1_16W_2: CLABCONF0: = SBC-MCM8PLUS; P/N: 161C0R751S
R66 = 2.2R,5%,0402,1_16W: CLABCONF0: DNP; P/N: 161C06R25S
R67 = 0R,_1206: CLABCONF0: = SBC-MCM8PLUS
R68 = 0R,_1206_1: CLABCONF0: = SBC-MCM8PLUS
R73 = 0R,_1206_3: CLABCONF0: = SBC-MCM8PLUS
R74 = 0R,_1206_2: CLABCONF0: = SBC-MCM8PLUS
R151 = 0R,_0402: CLABCONF0: = SBC-MCM8PLUS
TP_LVDS_DIMO = TESTPOINT: CLABCONF0: DNP
U5 = TPS61165DBVT: CLABCONF0: = SBC-MCM8PLUS; P/N: 123C15100S
U33 U38 = IP4220CZ6_0: CLABCONF0: = SBC-MCM8PLUS
C82 = 10nF,_25V,_X7R,_10%,_0402: CLABCONF0: = SBC-MCM8PLUS
C358 = 100nF,_10V,_X7R,_10%,_0402_2: CLABCONF0: = SBC-MCM8PLUS; P/N: 151C10500S
C359 = Cap_1uF,X5R,6.3V,0402: CLABCONF0: = SBC-MCM8PLUS
C360 = 100nF,_10V,_X7R,_10%,_0402: CLABCONF0: = SBC-MCM8PLUS; P/N: 151C10500S
D23-D25 = 1A_Schottky_Barrier_Rectifier: CLABCONF0: = SBC-MCM8PLUS
F4 = Fuse,_0.75A_Ih,_1.5A_It: CLABCONF0: = SBC-MCM8PLUS; P/N: 175P22200S
P14 = HDMI_Connector: CLABCONF0: = SBC-MCM8PLUS
Q24 = DUAL_N-MOSFET,_0.5A_20V: CLABCONF0: = SBC-MCM8PLUS
R152 R270 = RESISTOR: CLABCONF0: = SBC-MCM8PLUS; P/N: 161C20021S
R153 = RESISTOR: CLABCONF0: = SBC-MCM8PLUS; P/N: 161C10045S
R171 = RESISTOR: CLABCONF0: = SBC-MCM8PLUS; P/N: 161C12011S
R256 = RESISTOR: CLABCONF0: = SBC-MCM8PLUS; P/N: 161C47025S
R264 = RESISTOR: CLABCONF0: = SBC-MCM8PLUS; P/N: 161C27421S
R265 = 1K,1%,0402,1_16W_1: CLABCONF0: = SBC-MCM8PLUS
R266 = 1K,1%,0402,1_16W_2: CLABCONF0: = SBC-MCM8PLUS
R267 = 1K,1%,0402,1_16W_3: CLABCONF0: = SBC-MCM8PLUS
R268 = 1K,1%,0402,1_16W: CLABCONF0: = SBC-MCM8PLUS
R344 = 0R,_0402_1_4: CLABCONF0: = SBC-MCM8PLUS
R299 R345 R357 = 0R,_0402_1_2: CLABCONF0: = SBC-MCM8PLUS
R269 R339 R348 = 0R,_0402_1_1: CLABCONF0: = SBC-MCM8PLUS
R349 = 0R,_0402_1_6: CLABCONF0: = SBC-MCM8PLUS
R350 = 0R,_0402_1_5: CLABCONF0: = SBC-MCM8PLUS
R274 R301 R351 = 0R,_0402_1: CLABCONF0: = SBC-MCM8PLUS
R352 = 0R,_0402_1_3: CLABCONF0: = SBC-MCM8PLUS
R353 = 0R,_0402_1_7: CLABCONF0: = SBC-MCM8PLUS
R884 = 1K,1%,0402,1_16W_4: CLABCONF0: = SBC-MCM8PLUS
U9 U12 U13 U17 U44 = TXS0102_0: CLABCONF0: = SBC-MCM8PLUS; P/N: 116A01020S
C101 C105 = 100nF,_10V,_X7R,_10%,_0402_2: CLABCONF0: = SBC-MCM8PLUS
C106 C171 = 100nF,_10V,_X7R,_10%,_0402_10: CLABCONF0: = SBC-MCM8PLUS
C107 C853 = 100nF,_10V,_X7R,_10%,_0402_6: CLABCONF0: = SBC-MCM8PLUS
C104 C159 = 100nF,_10V,_X7R,_10%,_0402_8: CLABCONF0: = SBC-MCM8PLUS
C86 C164 = 100nF,_10V,_X7R,_10%,_0402_11: CLABCONF0: = SBC-MCM8PLUS
C84 C168 = 100nF,_10V,_X7R,_10%,_0402_5: CLABCONF0: = SBC-MCM8PLUS
C170 C895 = 100nF,_10V,_X7R,_10%,_0402_7: CLABCONF0: = SBC-MCM8PLUS
C850 C872 C873 C875 C876 C878 C879 C881 C894 C896 = 10uF,6_0.3V,0603,20%X5R: CLABCONF0: = SBC-MCM8PLUS
C87 C877 = 100nF,_10V,_X7R,_10%,_0402_9: CLABCONF0: = SBC-MCM8PLUS
C83 C880 = 100nF,_10V,_X7R,_10%,_0402_4: CLABCONF0: = SBC-MCM8PLUS
P48 P50 = Camera_20682-030E-02: CLABCONF0: = SBC-MCM8PLUS; P/N: 182K03002S
P49 P51 = FPC,_0.5mm,_22_cont_0.: CLABCONF0: = SBC-MCM8PLUS; P/N: 182P02201S
R212 R297 = 33R,5%,0402,1_16W: CLABCONF0: DNP
R276 R302 = 0R,_0402_0_3: CLABCONF0: DNP; P/N: 161C00005S
R303 R338 = 0R,_0402_0_6: CLABCONF0: = SBC-MCM8PLUS; P/N: 161C00005S
R313 = 10K,1%,0402,1_16W_7: CLABCONF0: = SBC-MCM8PLUS
R314 = 10K,1%,0402,1_16W_8: CLABCONF0: = SBC-MCM8PLUS
R94 R315 = 10K,1%,0402,1_16W_5: CLABCONF0: = SBC-MCM8PLUS
R79 R317 = 0R,_0402_0_5: CLABCONF0: = SBC-MCM8PLUS; P/N: 161C00005S
R128 R328 = 10K,1%,0402,1_16W_2: CLABCONF0: = SBC-MCM8PLUS
R340 = 10K,1%,0402,1_16W: CLABCONF0: = SBC-MCM8PLUS
R354 R366 = 0R,_0402_0_2: CLABCONF0: = SBC-MCM8PLUS; P/N: 161C00005S
R275 R355 = 0R,_0402_0_1: CLABCONF0: = SBC-MCM8PLUS; P/N: 161C00005S
R356 R359 = 0R,_0402_0_4: CLABCONF0: = SBC-MCM8PLUS; P/N: 161C00005S
R358 R365 = 0R,_0402_0: CLABCONF0: = SBC-MCM8PLUS; P/N: 161C00005S
U63 U64 = MAX14998ETOT: CLABCONF0: = SBC-MCM8PLUS
R92 = 4_0.75K,1%,0402,1_16W_1: CLABCONF0: = SBC-MCM8PLUS
R93 = 4_0.75K,1%,0402,1_16W: CLABCONF0: = SBC-MCM8PLUS
R360 = 0R,_0402_0_7: CLABCONF0: = SBC-MCM8PLUS; P/N: 161C00005S
H1-H5 = Hole,_Plated,_M2,_5mm._ext.: CLABCONF0: DNP
SP3 = SMT_SPACER_M2x3_1: CLABCONF0: = SBC-MCM8PLUS

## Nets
1V8_PER: C842.1 C850.1 C874.1 C875.1 P48.3(VCC_1P8) P50.3(VCC_1P8) R94.1 R275.1 R303.1 ; also on sheet 9 10 12 13 14 15
3V3_PER: C1.1 C27.1 C65.2 C87.1 C101.1 C104.2 C105.2 C159.2 C160.2 C164.1 C169.1 C170.2 C171.2 C174.2 C175.2 C191.1 C202.1 C853.1 C872.1 C873.1 C876.1 C877.1 C878.1 C879.1 C880.1 C881.1 C894.1 C895.1 C896.1 D24.2(ANODE) E16.1 E18.1 P5.3 P11.38 P11.39 P48.1(VCC1_3P3) P48.2(VCC2_3P3) P49.22 P50.1(VCC1_3P3) P50.2(VCC2_3P3) P51.22 Q24.2(G1) Q24.5(G2) R3.2 R54.1 R56.1 R60.1 R62.1 R152.2 R153.2 R160.1 R162.1 R163.1 R182.1 R188.1 R189.1 R190.1 R191.1 R200.1 R201.1 R265.1 R266.1 R270.1 R276.1 R302.1 U9.3(VCCA) U12.7(VCCB) U13.7(VCCB) U17.7(VCCB) U33.5(VBUS) U44.7(VCCB) U63.1(VDD) U63.6(VDD_1) U63.13(VDD_2) U63.26(VDD_3) U64.1(VDD) U64.6(VDD_1) U64.13(VDD_2) U64.26(VDD_3) ; also on sheet 9 10 11 12 13 14 15 16
5V0_PER: F4.2 R73.1 ; also on sheet 9 10 13 14 16
GND: C1.2 C2.2 C3.2 C4.2 C5.2 C6.2 C7.2 C8.2 C9.2 C10.2 C11.2 C12.2 C13.2 C21.2 C27.2 C55.2 C56.2 C57.2 C58.2 C64.1 C65.1 C67.1 C82.1 C83.2 C84.2 C86.2 C87.2 C101.2 C102.2 C104.1 C105.1 C106.2 C107.2 C125.2 C159.1 C160.1 C164.2 C168.2 C169.2 C170.1 C171.1 C174.1 C175.1 C191.2 C202.2 C340.2 C341.2 C342.2 C344.2 C345.2 C346.2 C359.2 C842.2 C850.2 C853.2 C872.2 C873.2 C874.2 C875.2 C876.2 C877.2 C878.2 C879.2 C880.2 C881.2 C894.2 C895.2 C896.2 H1.1 H2.1 H3.1 H4.1 H5.1 L1.5(GND) L1.6(GND) L2.5(GND) L2.6(GND) L7.5(GND) L7.6(GND) L12.5(GND) L12.6(GND) L13.5(GND) L13.6(GND) L25.5(GND) L25.6(GND) L27.5(GND) L27.6(GND) L28.5(GND) L28.6(GND) L29.5(GND) L29.6(GND) L30.5(GND) L30.6(GND) LGA1.A005 LGA1.A008 LGA1.A014 LGA1.A026 LGA1.A029 LGA1.A041 LGA1.A056 LGA1.A074 LGA1.A077 LGA1.A080 LGA1.A083 LGA1.A086 LGA1.A093 LGA1.A118 LGA1.A121 LGA1.A130 LGA1.A133 LGA1.A138 LGA1.B001 LGA1.B008 LGA1.B013 LGA1.B016 LGA1.B022 LGA1.B029 LGA1.B030 LGA1.B033 LGA1.B036 LGA1.B039 LGA1.B042 LGA1.B045 LGA1.B050 LGA1.B054 LGA1.B058 LGA1.B059 LGA1.B066 LGA1.B071 LGA1.B075 LGA1.B078 LGA1.B081 LGA1.B084 LGA1.B087 LGA1.B088 LGA1.B093 LGA1.B098 LGA1.B103 LGA1.B106 LGA1.B113 LGA1.B116 P5.1 P5.8 P5.9 P5.10 P11.11 P11.16 P11.19 P11.22 P11.25 P11.28 P11.31 P11.34 P14.2(D2_Shield) P14.5(D1_Shield) P14.8(D0_Shield) P14.11(CK_Shield) P14.17(GND) P14.20(SHELL1) P14.21(SHELL2) P48.4(GND1) P48.5(GND2) P48.9(GND3) P48.14(GND4) P48.17(GND5) P48.18(GND6) P48.22(GND7) P48.26(GND8) P48.SH1 P48.SH2 P48.SH3 P48.SH4 P48.SH5 P48.SH6 P48.SH7 P48.SH8 P48.SH9 P48.SH10 P48.SH11 P48.SH12 P48.SH13 P48.SH14 P48.SH15 P48.SH16 P48.SH17 P48.SH18 P48.SH19 P49.1 P49.4 P49.7 P49.10 P49.13 P49.16 P49.19 P49.NC1 P49.NC2 P50.4(GND1) P50.5(GND2) P50.9(GND3) P50.14(GND4) P50.17(GND5) P50.18(GND6) P50.22(GND7) P50.26(GND8) P50.SH1 P50.SH2 P50.SH3 P50.SH4 P50.SH5 P50.SH6 P50.SH7 P50.SH8 P50.SH9 P50.SH10 P50.SH11 P50.SH12 P50.SH13 P50.SH14 P50.SH15 P50.SH16 P50.SH17 P50.SH18 P50.SH19 P51.1 P51.4 P51.7 P51.10 P51.13 P51.16 P51.19 P51.NC1 P51.NC2 R55.2 R59.2 R61.2 R63.2 R64.2 R82.1 R87.1 R128.1 R129.1 R256.1 R313.1 R314.1 R316.1 R328.1 R341.1 R884.2 SP3.NC(1) SW5.1 SW5.3 SW6.1 SW6.3 U5.4(GND) U9.2(GND) U12.2(GND) U13.2(GND) U17.2(GND) U33.2(GND) U38.2(GND) U44.2(GND) U63.Tpad U64.Tpad ; also on sheet 9 10 11 12 13 14 15 16
VCC_RTC: LGA1.A023 ; also on sheet 13
VDD_3P3_CN: D24.1(CATHODE) R264.2
ALT_BOOT: E19.1 LGA1.A100 SW7.2 SW7.4
AUD_nINT/SAI3_RXFS: LGA1.B070 ; also on sheet 9
CAN1_RX/SAI2_TXC: LGA1.B083 ; also on sheet 10
CAN1_TX/SAI2_RXC: LGA1.B082 ; also on sheet 10
CAN2_RX/SAI2_MCLK: LGA1.B080 ; also on sheet 10
CAN2_TX/SAI2_TXD0: LGA1.B079 ; also on sheet 10
CLAB_RESERVED1: LGA1.A055 ; also on sheet 15
CN_LVDS_DISP_RESET: C64.2 P11.36 R3.1 R151.2
CSI1_B_FLASH_OUT: R339.2 U13.1(B2) ; also on sheet 10
CSI1_B_FLASH_OUT_1V8: P48.29(FLASH) R301.1
CSI1_B_RST: R340.2 ; also on sheet 10
CSI1_B_RST_1V8: P48.21(RESET) R340.1 R341.2
CSI1_B_TRG: U13.8(B1) ; also on sheet 10
CSI1_B_TRG_1V8: P48.12(TRIGGER) R299.1
CSI1_GPIO_1V8_ENABLE: R313.2 R327.1 U13.6(OE)
CSI1_I2C_1V8_ENABLE: R314.2 R329.1 U44.6(OE)
CSI1_MCLK_B: P48.13(RSVD1) R297.2
CSI1_P48_CKN: P48.24(MIPI_CLK_N) U63.31(NO1-)
CSI1_P48_CKP: P48.25(MIPI_CLK_P) U63.32(NO1+)
CSI1_P48_DN0: P48.19(MIPI_D0_N) U63.29(NO2-)
CSI1_P48_DN1: P48.15(MIPI_D1_N) U63.27(NO3-)
CSI1_P48_DN2: P48.10(MIPI_D2_N) U63.20(NO4-)
CSI1_P48_DN3: P48.27(MIPI_D3_N) U63.33(NO0-)
CSI1_P48_DP0: P48.20(MIPI_D0_P) U63.30(NO2+)
CSI1_P48_DP1: P48.16(MIPI_D1_P) U63.28(NO3+)
CSI1_P48_DP2: P48.11(MIPI_D2_P) U63.21(NO4+)
CSI1_P48_DP3: P48.28(MIPI_D3_P) U63.34(NO0+)
CSI1_P49_CKN: P49.8 U63.39(NC1-)
CSI1_P49_CKP: P49.9 U63.40(NC1+)
CSI1_P49_DN0: P49.2 U63.37(NC2-)
CSI1_P49_DN1: P49.5 U63.35(NC3-)
CSI1_P49_DN2: P49.11 U63.24(NC4-)
CSI1_P49_DN3: P49.14 U63.41(NC0-)
CSI1_P49_DP0: P49.3 U63.38(NC2+)
CSI1_P49_DP1: P49.6 U63.36(NC3+)
CSI1_P49_DP2: P49.12 U63.25(NC4+)
CSI1_P49_DP3: P49.15 U63.42(NC0+)
CSI1_P49_I2C_SCL: P49.20 R354.2
CSI1_P49_I2C_SDA: P49.21 R355.2
CSI1_PWR_DWN_B: R315.2 R317.1 ; also on sheet 10
CSI1_PWR_DWN_B_1V8: P48.6(PWDN) R315.1 R316.2
CSI1_SELECTOR: E18.2 R327.2 R328.2 R329.2 U63.16(SEL1) U63.17(SEL2)
CSI2_B_FLASH_OUT: R357.2 U12.1(B2) ; also on sheet 10
CSI2_B_FLASH_OUT_1V8: P50.29(FLASH) R274.1
CSI2_B_RST: R239.2 ; also on sheet 10
CSI2_B_RST_1V8: P50.21(RESET) R128.2 R239.1
CSI2_B_TRG: U12.8(B1) ; also on sheet 10
CSI2_B_TRG_1V8: P50.12(TRIGGER) R269.1
CSI2_LSGPIO_OE: R79.2 R87.2 U12.6(OE)
CSI2_MCLK_B: P50.13(RSVD1) R212.2
CSI2_P50_CKN: P50.24(MIPI_CLK_N) U64.31(NO1-)
CSI2_P50_CKP: P50.25(MIPI_CLK_P) U64.32(NO1+)
CSI2_P50_DN0: P50.19(MIPI_D0_N) U64.29(NO2-)
CSI2_P50_DN1: P50.15(MIPI_D1_N) U64.27(NO3-)
CSI2_P50_DN2: P50.10(MIPI_D2_N) U64.20(NO4-)
CSI2_P50_DN3: P50.27(MIPI_D3_N) U64.33(NO0-)
CSI2_P50_DP0: P50.20(MIPI_D0_P) U64.30(NO2+)
CSI2_P50_DP1: P50.16(MIPI_D1_P) U64.28(NO3+)
CSI2_P50_DP2: P50.11(MIPI_D2_P) U64.21(NO4+)
CSI2_P50_DP3: P50.28(MIPI_D3_P) U64.34(NO0+)
CSI2_P51_CKN: P51.8 U64.39(NC1-)
CSI2_P51_CKP: P51.9 U64.40(NC1+)
CSI2_P51_DN0: P51.2 U64.37(NC2-)
CSI2_P51_DN1: P51.5 U64.35(NC3-)
CSI2_P51_DN2: P51.11 U64.24(NC4-)
CSI2_P51_DN3: P51.14 U64.41(NC0-)
CSI2_P51_DP0: P51.3 U64.38(NC2+)
CSI2_P51_DP1: P51.6 U64.36(NC3+)
CSI2_P51_DP2: P51.12 U64.25(NC4+)
CSI2_P51_DP3: P51.15 U64.42(NC0+)
CSI2_P51_I2C_SCL: P51.20 R365.2
CSI2_P51_I2C_SDA: P51.21 R366.2
CSI2_PWR_DWN_B: R273.2 R338.1 ; also on sheet 10
CSI2_PWR_DWN_B_1V8: P50.6(PWDN) R129.2 R273.1
CSI2_SCCB_EN: C102.1 R94.2 U17.6(OE)
CSI2_SELECTOR: E16.2 R82.2 U64.16(SEL1) U64.17(SEL2)
DSI_TP_INT/SAI5_RXD1: LGA1.A035 ; also on sheet 11
EARC_N: C358.2 L29.3 R171.2
EARC_N_HPD: C358.1 LGA1.B049
EARC_P: C360.2 L29.4
EARC_P_UTIL: C360.1 LGA1.B051
ECSPI1_MISO: LGA1.B091 ; also on sheet 10
ECSPI1_MOSI: LGA1.B092 ; also on sheet 10
ECSPI1_SCLK: LGA1.B089 ; also on sheet 10
ECSPI1_SS0: LGA1.B090 ; also on sheet 10
ECSPI2_MISO: LGA1.B064 ; also on sheet 10
ECSPI2_MOSI: LGA1.B063 ; also on sheet 10
ECSPI2_SCLK: LGA1.B065 ; also on sheet 10
ECSPI2_SS0: LGA1.B062 ; also on sheet 10
ENET1_EV0_IN/SAI1_RXFS: LGA1.B105 ; also on sheet 9
ENET1_EV0_OUT/SAI1_RXC: LGA1.B104 ; also on sheet 9
ENET1_EV1_IN/SAI1_RXD0: LGA1.B102 ; also on sheet 9
ENET1_EV1_OUT/SAI1_RXD1: LGA1.B101 ; also on sheet 9
ENET1_MDC/SAI1_RXD2: LGA1.B100 ; also on sheet 9
ENET1_MDIO/SAI1_RXD3: LGA1.B099 ; also on sheet 9
ENET1_nINT/SAI3_TXFS: LGA1.B074 ; also on sheet 9
ENET1_nRST/SAI3_TXC: LGA1.B076 ; also on sheet 9
ENET1_nWOL/SAI3_TXD: LGA1.B077 ; also on sheet 9
ENET1_RD0/SAI1_RXD4: LGA1.A088 ; also on sheet 9
ENET1_RD1/SAI1_RXD5: LGA1.A089 ; also on sheet 9
ENET1_RD2/SAI1_RXD6: LGA1.A090 ; also on sheet 9
ENET1_RD3/SAI1_RXD7: LGA1.A091 ; also on sheet 9
ENET1_RX_CTL/SAI1_TXFS: LGA1.A092 ; also on sheet 9
ENET1_RX_ERR/SAI1_TXD6: LGA1.B108 ; also on sheet 9
ENET1_RXC/SAI1_TXC: LGA1.A087 ; also on sheet 9
ENET1_TD0/SAI1_TXD0: LGA1.A095 ; also on sheet 9
ENET1_TD1/SAI1_TXD1: LGA1.A096 ; also on sheet 9
ENET1_TD2/SAI1_TXD2: LGA1.A097 ; also on sheet 9
ENET1_TD3/SAI1_TXD3: LGA1.A098 ; also on sheet 9
ENET1_TX_CLK/SAI1_MCLK: LGA1.B047 ; also on sheet 9
ENET1_TX_CTL/SAI1_TXD4: LGA1.A099 ; also on sheet 9
ENET1_TX_ERR/SAI1_TXD7: LGA1.B107 ; also on sheet 10 16
ENET1_TXC/SAI1_TXD5: LGA1.A094 ; also on sheet 9
ENET_INT/GPIO1_11: LGA1.B017 ; also on sheet 9
ENET_MDC: LGA1.A061 ; also on sheet 9
ENET_MDIO: LGA1.A060 ; also on sheet 9
ENET_nRST/GPIO1_10: LGA1.B067 ; also on sheet 9
ENET_RD0: LGA1.A067 ; also on sheet 9
ENET_RD1: LGA1.A066 ; also on sheet 9
ENET_RD2: LGA1.A063 ; also on sheet 9
ENET_RD3: LGA1.A062 ; also on sheet 9
ENET_RX_CTL: LGA1.A065 ; also on sheet 9
ENET_RXC: LGA1.A064 ; also on sheet 9
ENET_TD0: LGA1.A070 ; also on sheet 9
ENET_TD1: LGA1.A068 ; also on sheet 9
ENET_TD2: LGA1.A072 ; also on sheet 9
ENET_TD3: LGA1.A069 ; also on sheet 9
ENET_TX_CTL: LGA1.A071 ; also on sheet 9
ENET_TXC: LGA1.A073 ; also on sheet 9
ENET_VIO: C125.1 LGA1.A059 ; also on sheet 10
ENET_WOL/GPIO1_13: LGA1.B006 ; also on sheet 9
EXP_RST/GPIO1_08: LGA1.B010 ; also on sheet 10
EXT_NVCC_SNVS_1P8: LGA1.B002 ; also on sheet 10
FLEXSPI_BOOT: E20.2 R191.2
FPC49_17: P49.17 R317.2
FPC49_18: P49.18 R339.1
FPC51_17: P51.17 R338.2
FPC51_18: P51.18 R357.1
GPIO1_00: LGA1.B009 ; also on sheet 10
GPIO1_01: LGA1.B012 ; also on sheet 10
GPIO1_05: LGA1.B004 ; also on sheet 10
GPIO1_06: LGA1.B003 ; also on sheet 10
GPIO1_15: LGA1.B007 ; also on sheet 10
GPIO2_06/SD1_DATA4: LGA1.A057 ; also on sheet 15
GPIO2_07/SD1_DATA5: LGA1.A052 ; also on sheet 15
GPIO2_08/SD1_DATA6: LGA1.A053 ; also on sheet 15
GPIO2_09/SD1_DATA7: LGA1.A058 ; also on sheet 15
GPIO2_19/SD2_RESET_B: LGA1.A101 ; also on sheet 10
GPIO3_23/SAI5_RXD2: LGA1.B019 ; also on sheet 10
GPIO3_24/SAI5_RXD3: LGA1.B005 ; also on sheet 10
GPIO4_21/SAI2_RXFS: LGA1.B109 ; also on sheet 10
GPIO4_23/SAI2_RXD0: LGA1.B068 ; also on sheet 10
GPIO4_24/SAI2_TXFS: LGA1.B110 ; also on sheet 10
GPIO5_20/I2C4_SCL: LGA1.B015 R163.2 ; also on sheet 10 12
GPIO5_21/I2C4_SDA: LGA1.B014 R201.2 ; also on sheet 10 12
HDMI_5V_FL: C359.1 D23.2(ANODE) F4.1
HDMI_5VSCHT: C67.2 C82.2 D23.1(CATHODE) P14.18(+5V) R267.1 R268.1 R884.1 U9.7(VCCB) U38.1(IO1) U38.5(VBUS)
HDMI_CEC: D25.2(ANODE) LGA1.B061 Q24.4(S2) R152.1
HDMI_CEC_3P3: D25.1(CATHODE) P14.13(CE_Remote) Q24.3(D2) R264.1 U38.6(IO4)
HDMI_DDC_SCL: LGA1.B052 R266.2 U9.5(A1)
HDMI_DDC_SDA: LGA1.B053 R265.2 U9.4(A2)
HDMI_HPD: LGA1.B060 Q24.1(S1) R153.1
HDMI_HPD_5V: Q24.6(D1) R171.1 R256.2
HDMI_HPD_CN: L29.2 P14.19(HP_DET)
HDMI_TX0N: LGA1.A081 R351.2
HDMI_TX0P: LGA1.A082 R350.2
HDMI_TX1N: LGA1.A078 R349.2
HDMI_TX1P: LGA1.A079 R348.2
HDMI_TX2N: LGA1.A075 R345.2
HDMI_TX2P: LGA1.A076 R344.2
HDMI_TXCN: LGA1.A084 R353.2
HDMI_TXCP: LGA1.A085 R352.2
HDMI_UTILITY_CN: L29.1 P14.14(NC)
I2C3_SCL: LGA1.B115 R162.2 ; also on sheet 9 10
I2C3_SDA: LGA1.B114 R200.2 ; also on sheet 9 10
I2C5_3V3_SCL: R358.2 U44.1(B2)
I2C5_3V3_SDA: R356.2 U44.8(B1)
I2C5_SCL/SAI5_RXD0: LGA1.B094 R188.2 R354.1 R358.1 ; also on sheet 10 11
I2C5_SCL_1V8: P48.7(I2C_SCL) R105.2 U44.4(A2)
I2C5_SDA/SAI5_MCLK: LGA1.B095 R160.2 R355.1 R356.1 ; also on sheet 10 11
I2C5_SDA_1V8: P48.8(I2C_SDA) R104.2 U44.5(A1)
I2C6_SCL: P5.4 R360.1 R365.1 U33.1(IO1)
I2C6_SCL/SAI5_RXFS: LGA1.B097 R190.2 ; also on sheet 10
I2C6_SCL_1V8: P50.7(I2C_SCL) R93.2 U17.4(A2)
I2C6_SCL_3V3: R360.2 U17.1(B2)
I2C6_SDA: P5.5 R359.1 R366.1 U33.3(IO2)
I2C6_SDA/SAI5_RXC: LGA1.B096 R189.2 ; also on sheet 10
I2C6_SDA_1V8: P50.8(I2C_SDA) R92.2 U17.5(A1)
I2C6_SDA_3V3: R359.2 U17.8(B1)
JTAG_MOD: LGA1.A042 ; also on sheet 10
JTAG_TCK: LGA1.A043 ; also on sheet 10
JTAG_TDI: LGA1.A045 ; also on sheet 10
JTAG_TDO: LGA1.A044 ; also on sheet 10
JTAG_TMS: LGA1.A046 ; also on sheet 10
LVDS0_CLK_N: L13.3 LGA1.B038
LVDS0_CLK_P: L13.4 LGA1.B037
LVDS0_CLKN: L13.2 P11.24
LVDS0_CLKP: L13.1 P11.23
LVDS0_D0_N: L2.4 LGA1.B032
LVDS0_D0_P: L2.3 LGA1.B031
LVDS0_D1_N: L1.4 LGA1.B035
LVDS0_D1_P: L1.3 LGA1.B034
LVDS0_D2_N: L7.4 LGA1.B041
LVDS0_D2_P: L7.3 LGA1.B040
LVDS0_D3_N: L12.4 LGA1.B044
LVDS0_D3_P: L12.3 LGA1.B043
LVDS0_N0: L2.1 P11.33
LVDS0_N1: L1.1 P11.30
LVDS0_N2: L7.1 P11.27
LVDS0_N3: L12.1 P11.21
LVDS0_P0: L2.2 P11.32
LVDS0_P1: L1.2 P11.29
LVDS0_P2: L7.2 P11.26
LVDS0_P3: L12.2 P11.20
LVDS_COMP: C58.1 U5.5(COMP)
LVDS_DIMO: P11.14 TP_LVDS_DIMO.1
LVDS_DISP_RESET: R151.1 ; also on sheet 10
LVDS_L_R: P11.8 R56.2 R59.1
LVDS_LED_EN: R52.2 R74.2 U5.2(CTRL)
LVDS_LED_N: R65.1 R66.1 R68.2 U5.6(FB)
LVDS_LED_NEG: C85.1 P11.9 P11.10 R68.1
LVDS_LED_P: C57.1 D11.CATHODE R67.2
LVDS_LED_POS: C85.2 P11.1 P11.2 R67.1
LVDS_RESET: R63.1 R65.2 R66.2
LVDS_SELB: P11.13 R62.2 R64.1
LVDS_STBYB: P11.35 R54.2 R55.1
LVDS_SW_PWR_IN: C55.1 C56.1 L9.1 R52.1 R73.2 U5.1(IN)
LVDS_TOUCH_RESET: P5.7 U33.6(IO4) ; also on sheet 10
LVDS_TP_INT/SD2_WP: LGA1.A105 P5.6 U33.4(IO3)
LVDS_U_D: P11.7 R60.2 R61.1
LVDS_WLD_SW: D11.ANODE L9.2 U5.3(SW)
MIPI_CSI1_CLK_N: LGA1.A006 U63.5(COM1-)
MIPI_CSI1_CLK_P: LGA1.A007 U63.4(COM1+)
MIPI_CSI1_D0_N: LGA1.A011 U63.8(COM2-)
MIPI_CSI1_D0_P: LGA1.A012 U63.7(COM2+)
MIPI_CSI1_D1_N: LGA1.A009 U63.10(COM3-)
MIPI_CSI1_D1_P: LGA1.A010 U63.9(COM3+)
MIPI_CSI1_D2_N: LGA1.A003 U63.12(COM4-)
MIPI_CSI1_D2_P: LGA1.A004 U63.11(COM4+)
MIPI_CSI1_D3_N: LGA1.A001 U63.3(COM0-)
MIPI_CSI1_D3_P: LGA1.A002 U63.2(COM0+)
MIPI_CSI2_CLK_N: LGA1.A131 U64.5(COM1-)
MIPI_CSI2_CLK_P: LGA1.A132 U64.4(COM1+)
MIPI_CSI2_D0_N: LGA1.A136 U64.8(COM2-)
MIPI_CSI2_D0_P: LGA1.A137 U64.7(COM2+)
MIPI_CSI2_D1_N: LGA1.A134 U64.10(COM3-)
MIPI_CSI2_D1_P: LGA1.A135 U64.9(COM3+)
MIPI_CSI2_D2_N: LGA1.A128 U64.12(COM4-)
MIPI_CSI2_D2_P: LGA1.A129 U64.11(COM4+)
MIPI_CSI2_D3_N: LGA1.A126 U64.3(COM0-)
MIPI_CSI2_D3_P: LGA1.A127 U64.2(COM0+)
MIPI_DSI1_CLK_N: LGA1.A119 ; also on sheet 11
MIPI_DSI1_CLK_P: LGA1.A120 ; also on sheet 11
MIPI_DSI1_D0_N: LGA1.A114 ; also on sheet 11
MIPI_DSI1_D0_P: LGA1.A115 ; also on sheet 11
MIPI_DSI1_D1_N: LGA1.A116 ; also on sheet 11
MIPI_DSI1_D1_P: LGA1.A117 ; also on sheet 11
MIPI_DSI1_D2_N: LGA1.A122 ; also on sheet 11
MIPI_DSI1_D2_P: LGA1.A123 ; also on sheet 11
MIPI_DSI1_D3_N: LGA1.A124 ; also on sheet 11
MIPI_DSI1_D3_P: LGA1.A125 ; also on sheet 11
OE_DDC_LS: R270.2 U9.6(OE)
PCIE_REF_CLKN: LGA1.A020 ; also on sheet 12
PCIE_REF_CLKP: LGA1.A019 ; also on sheet 12
PCIE_RX_N: LGA1.A017 ; also on sheet 12
PCIE_RX_P: LGA1.A018 ; also on sheet 12
PCIE_TX_N: LGA1.A016 ; also on sheet 12
PCIE_TX_P: LGA1.A015 ; also on sheet 12
PMIC_ON_REQ: LGA1.B046 ; also on sheet 10 13
PMIC_STBY_REQ: LGA1.A013 ; also on sheet 10 13
PWM1_OUT/SPDIF_EXT_CLK: LGA1.B055 ; also on sheet 11
PWM2_OUT/SPDIF_RX: LGA1.B056 R74.1 ; also on sheet 10
PWRBTN: LGA1.A033 SW5.2 SW5.4
QSPI_BOOT_EN_3P3: E20.1 LGA1.B048
QSPIA_DATA0/NAND_DATA00: LGA1.B028 ; also on sheet 14
QSPIA_DATA1/NAND_DATA01: LGA1.B027 ; also on sheet 14
QSPIA_DATA2/NAND_DATA02: LGA1.B026 ; also on sheet 14
QSPIA_DATA3/NAND_DATA03: LGA1.B025 ; also on sheet 14
QSPIA_SCLK/NAND_ALE: LGA1.B023 ; also on sheet 14
QSPIA_SS0/NAND_CE0_B: LGA1.B024 ; also on sheet 14
SAI3_MCLK: LGA1.B069 ; also on sheet 9
SAI3_RXC/UART2_CTS: LGA1.B072 ; also on sheet 9
SAI3_RXD/UART2_RTS: LGA1.B073 ; also on sheet 9
SD1_CLK: LGA1.A049 ; also on sheet 15
SD1_CMD: LGA1.A047 ; also on sheet 15
SD1_DATA0: LGA1.A054 ; also on sheet 15
SD1_DATA1: LGA1.A051 ; also on sheet 15
SD1_DATA2: LGA1.A050 ; also on sheet 15
SD1_DATA3: LGA1.A048 ; also on sheet 15
SD2_CLK: LGA1.A106 ; also on sheet 14
SD2_CMD: LGA1.A107 ; also on sheet 14
SD2_DATA0: LGA1.A104 ; also on sheet 14
SD2_DATA1: LGA1.A103 ; also on sheet 14
SD2_DATA2: LGA1.A108 ; also on sheet 14
SD2_DATA3: LGA1.A109 ; also on sheet 14
SD2_nCD: LGA1.A102 ; also on sheet 14
SPDIF_TX: LGA1.B057 ; also on sheet 10
SW_ALT_BOOT: E19.2 R182.2 SW7.1 SW7.3
SYS_I2C_SCL: LGA1.A025 ; also on sheet 10 12 14
SYS_I2C_SDA: LGA1.A024 ; also on sheet 10 12 14
SYS_RST_PMIC: LGA1.A022 SW6.2 SW6.4 ; also on sheet 10
TMDS1_CLK_CN: L30.3 R353.1
TMDS1_CLK_CP: L30.4 R352.1
TMDS1_CLK_LN: L30.2 P14.12(CK-)
TMDS1_CLK_LP: L30.1 P14.10(CK+)
TMDS1_DCLK: P14.15(DDC_CLK) R267.2 U9.8(B1) U38.4(IO3)
TMDS1_DDAT: P14.16(DDC_DATA) R268.2 U9.1(B2) U38.3(IO2)
TMDS1_TX0_CN: L28.3 R351.1
TMDS1_TX0_CP: L28.4 R350.1
TMDS1_TX0_LN: L28.2 P14.9(D0-)
TMDS1_TX0_LP: L28.1 P14.7(D0+)
TMDS1_TX1_CN: L25.3 R349.1
TMDS1_TX1_CP: L25.4 R348.1
TMDS1_TX1_LN: L25.2 P14.6(D1-)
TMDS1_TX1_LP: L25.1 P14.4(D1+)
TMDS1_TX2_CN: L27.3 R345.1
TMDS1_TX2_CP: L27.4 R344.1
TMDS1_TX2_LN: L27.2 P14.3(D2-)
TMDS1_TX2_LP: L27.1 P14.1(D2+)
U12_A2: R269.2 U12.5(A1)
U12_A4: R274.2 U12.4(A2)
U13_A1: R299.2 U13.5(A1)
U13_A2: R301.2 U13.4(A2)
UART1_RXD: LGA1.B085 ; also on sheet 10
UART1_TXD: LGA1.B086 ; also on sheet 10
UART2_RXD: LGA1.A112 ; also on sheet 10 14
UART2_TXD: LGA1.A113 ; also on sheet 10 14
UART3_RXD: LGA1.B112 ; also on sheet 10 14
UART3_TXD: LGA1.B111 ; also on sheet 10 14
UART4_RXD: LGA1.A110 ; also on sheet 10 14
UART4_TXD: LGA1.A111 ; also on sheet 10 14
USB1_DN: LGA1.A036 ; also on sheet 16
USB1_DP: LGA1.A037 ; also on sheet 16
USB1_ID/GPIO1_07: LGA1.B011 ; also on sheet 10 16
USB1_RX_N: LGA1.A139 ; also on sheet 16
USB1_RX_P: LGA1.A140 ; also on sheet 16
USB1_TX_N: LGA1.B020 ; also on sheet 16
USB1_TX_P: LGA1.B021 ; also on sheet 16
USB1_VBUS: LGA1.A034 ; also on sheet 16
USB2_DN: LGA1.A039 ; also on sheet 16
USB2_DP: LGA1.A040 ; also on sheet 16
USB2_RX_N: LGA1.A030 ; also on sheet 16
USB2_RX_P: LGA1.A031 ; also on sheet 16
USB2_TX_N: LGA1.A027 ; also on sheet 16
USB2_TX_P: LGA1.A028 ; also on sheet 16
USB2_VBUS: LGA1.A038 ; also on sheet 16
V_SOM: C2.1 C3.1 C4.1 C5.1 C6.1 C7.1 C8.1 C9.1 C10.1 C11.1 C12.1 C13.1 C21.1 C340.1 C341.1 C342.1 C344.1 C345.1 C346.1 LGA1.A021 LGA1.A032 LGA1.B018 ; also on sheet 10 13
VIO_CAMERA_CSI1: C106.1 C107.1 C168.1 R104.1 R105.1 R302.2 R303.2 U13.3(VCCA) U44.3(VCCA)
VIO_CAMERA_CSI2: C83.1 C84.1 C86.1 R79.1 R92.1 R93.1 R275.2 R276.2 U12.3(VCCA) U17.3(VCCA)

Not connected (* = marked no-connect by the designer): P5 2*; P11 3* 4* 5* 6* 12* 15* 17* 18* 37* 40*; P48 23(RSVD2)* 30(RSVD3)*; P50 23(RSVD2)* 30(RSVD3)*; R212 1*; R297 1*; U63 14(COM5+)* 15(COM5-)* 18(NO5-)* 19(NO5+)* 22(NC5-)* 23(NC5+)*; U64 14(COM5+)* 15(COM5-)* 18(NO5-)* 19(NO5+)* 22(NC5-)* 23(NC5+)*

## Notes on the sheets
sheet 1
- For PCIe module
- For LGA1 heatsink stand-offs
- For P15 (RGMII/I2S Extender)
sheet 2
- I2C4/5/6 PU provision
- DNP
- DNP
- DNP
- DNP
- SILKSCREEN ON BOTTOM SIDE:
- B001 ->
- B030 ->
- B088 ->
- <- B059
sheet 3
- Soldered External Interface
- V_SOM decoupling capacitors
- A036 ->
- Place close to MCM-iMX8M-Plus mount place
- A001 ->
- Serial Download
- SILKSCREEN: POWER
- A53 core debug
- M7 core debug
- SILKSCREEN: RESET
- A106 ->
- <- A070
- SILKSCREEN: ALT_BOOT
- SILKSCREEN: FlexSPI_ALT_BOOT
sheet 4
- MIPI-CSI2 Connectors
- SILKSCREEN:
  MIPI-CSI2 (22-pin, 3.3V)
- # 100-Ohm diff pairs
- SILKSCREEN:
  Enable 30-pin conn.
- 22-pin Connector for RPi cameras
  Four MIPI-CSI lanes connected
- SILKSCREEN:
  MIPI-CSI2 (30-pin, 1.8V)
- OE VCCA
  domain
- DNP
- DNP
- DNP
- # 100-Ohm diff pairs
- 30 pin Connector for
  e-CAM130_iMX8M
sheet 5
- MIPI-CSI1 Connectors
- SILKSCREEN:
  MIPI-CSI1 (22-pin, 3.3V)
- # 100-Ohm diff pairs
- SILKSCREEN:
  Enable 30-pin conn.
- # 100-Ohm diff pairs
- 22-pin Connector for RPi cameras
  Four MIPI-CSI lanes connected
- R327,R313 - 3.3->1.8 Divider
- OE VCCA
  domain
- SILKSCREEN:
  MIPI-CSI1 (30-pin, 1.8V)
- DNP
- DNP
- DNP
- R329,R314 - 3.3->1.8 Divider
- # 100-Ohm diff pairs
- DNP
- 30 pin Connector for e-CAM130_iMX8M
  (e-con System)
sheet 6
- HDMI connector with eARC
- # 100-Ohm diff pairs
- # 100-Ohm diff pairs
- # 100-Ohm diff pairs
- SILKSCREEN:
  HDMI 2.0 (eARC)
- eARC ESD and HPD DC Filter
- # 100-Ohm diff pairs
- DDC Level Shifter
- HPD and CEC Level Shifter
sheet 7
- LVDS connector
- LCD back-light power
- DNP
- DNP
- # 100-Ohm diff pairs
- # 100-Ohm diff pairs
- DNP
- DNP
- DNP
- SILKSCREEN:
  LVDS LCD
- DNP
- LVDS Touch-panel connector
- SILKSCREEN:
  LVDS Touch Ctl.
- Pinout of J5 reversed
   to FPC
- GT911 supports two I2C slave
  addresses: 0xBA/0xBB and 0x28/0x29.
  The host can select the address by
  changing the status of Reset and INT
  pins during the power-on
  initialization phase, refer:
  139D10090 Data Sheet, page 16
sheet 8
- SBC-MCM8PLUS
- BOARD REVISION: 1.0
- Page
- Description
- 01
- Block Diagram
- 02
- External Carrier-board interface
- 03
- Internal Carrier-board interface
- 04
- ENET-RTL8211, ENET1-RGMII
- 05
- USB3.0, Type-C, Host
- 06
- JTAG, CAN, GPIO Exp., Misc.
- 07
- MIPI-DSI LCD
- 08
- LVDS LCD
- 09
- HDMI, eARC
- 10
- MIPI-CSI1 Connectors
- 11
- MIPI-CSI2 Connectors
- 12
- mPCIE Connector
- 13
- Power
- 14
- UARTs, uSD, FlexSPI, etc.
- 15
- WiFi + BT on SDHC1
- 16
- Mechanical
- SILKSCREEN:
  CompuLab
  SBC-MCM8PLUS, Rev. 1.0
  188C04400
